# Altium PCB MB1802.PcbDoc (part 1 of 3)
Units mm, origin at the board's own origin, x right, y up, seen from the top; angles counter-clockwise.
Board outline 70 x 70 mm, 4 copper layers (Top Layer, Signal Layer 1, Signal Layer 2, Bottom Layer), stack 1.56 mm thick; 220 components, 159 nets, 974 pads, 563 vias.
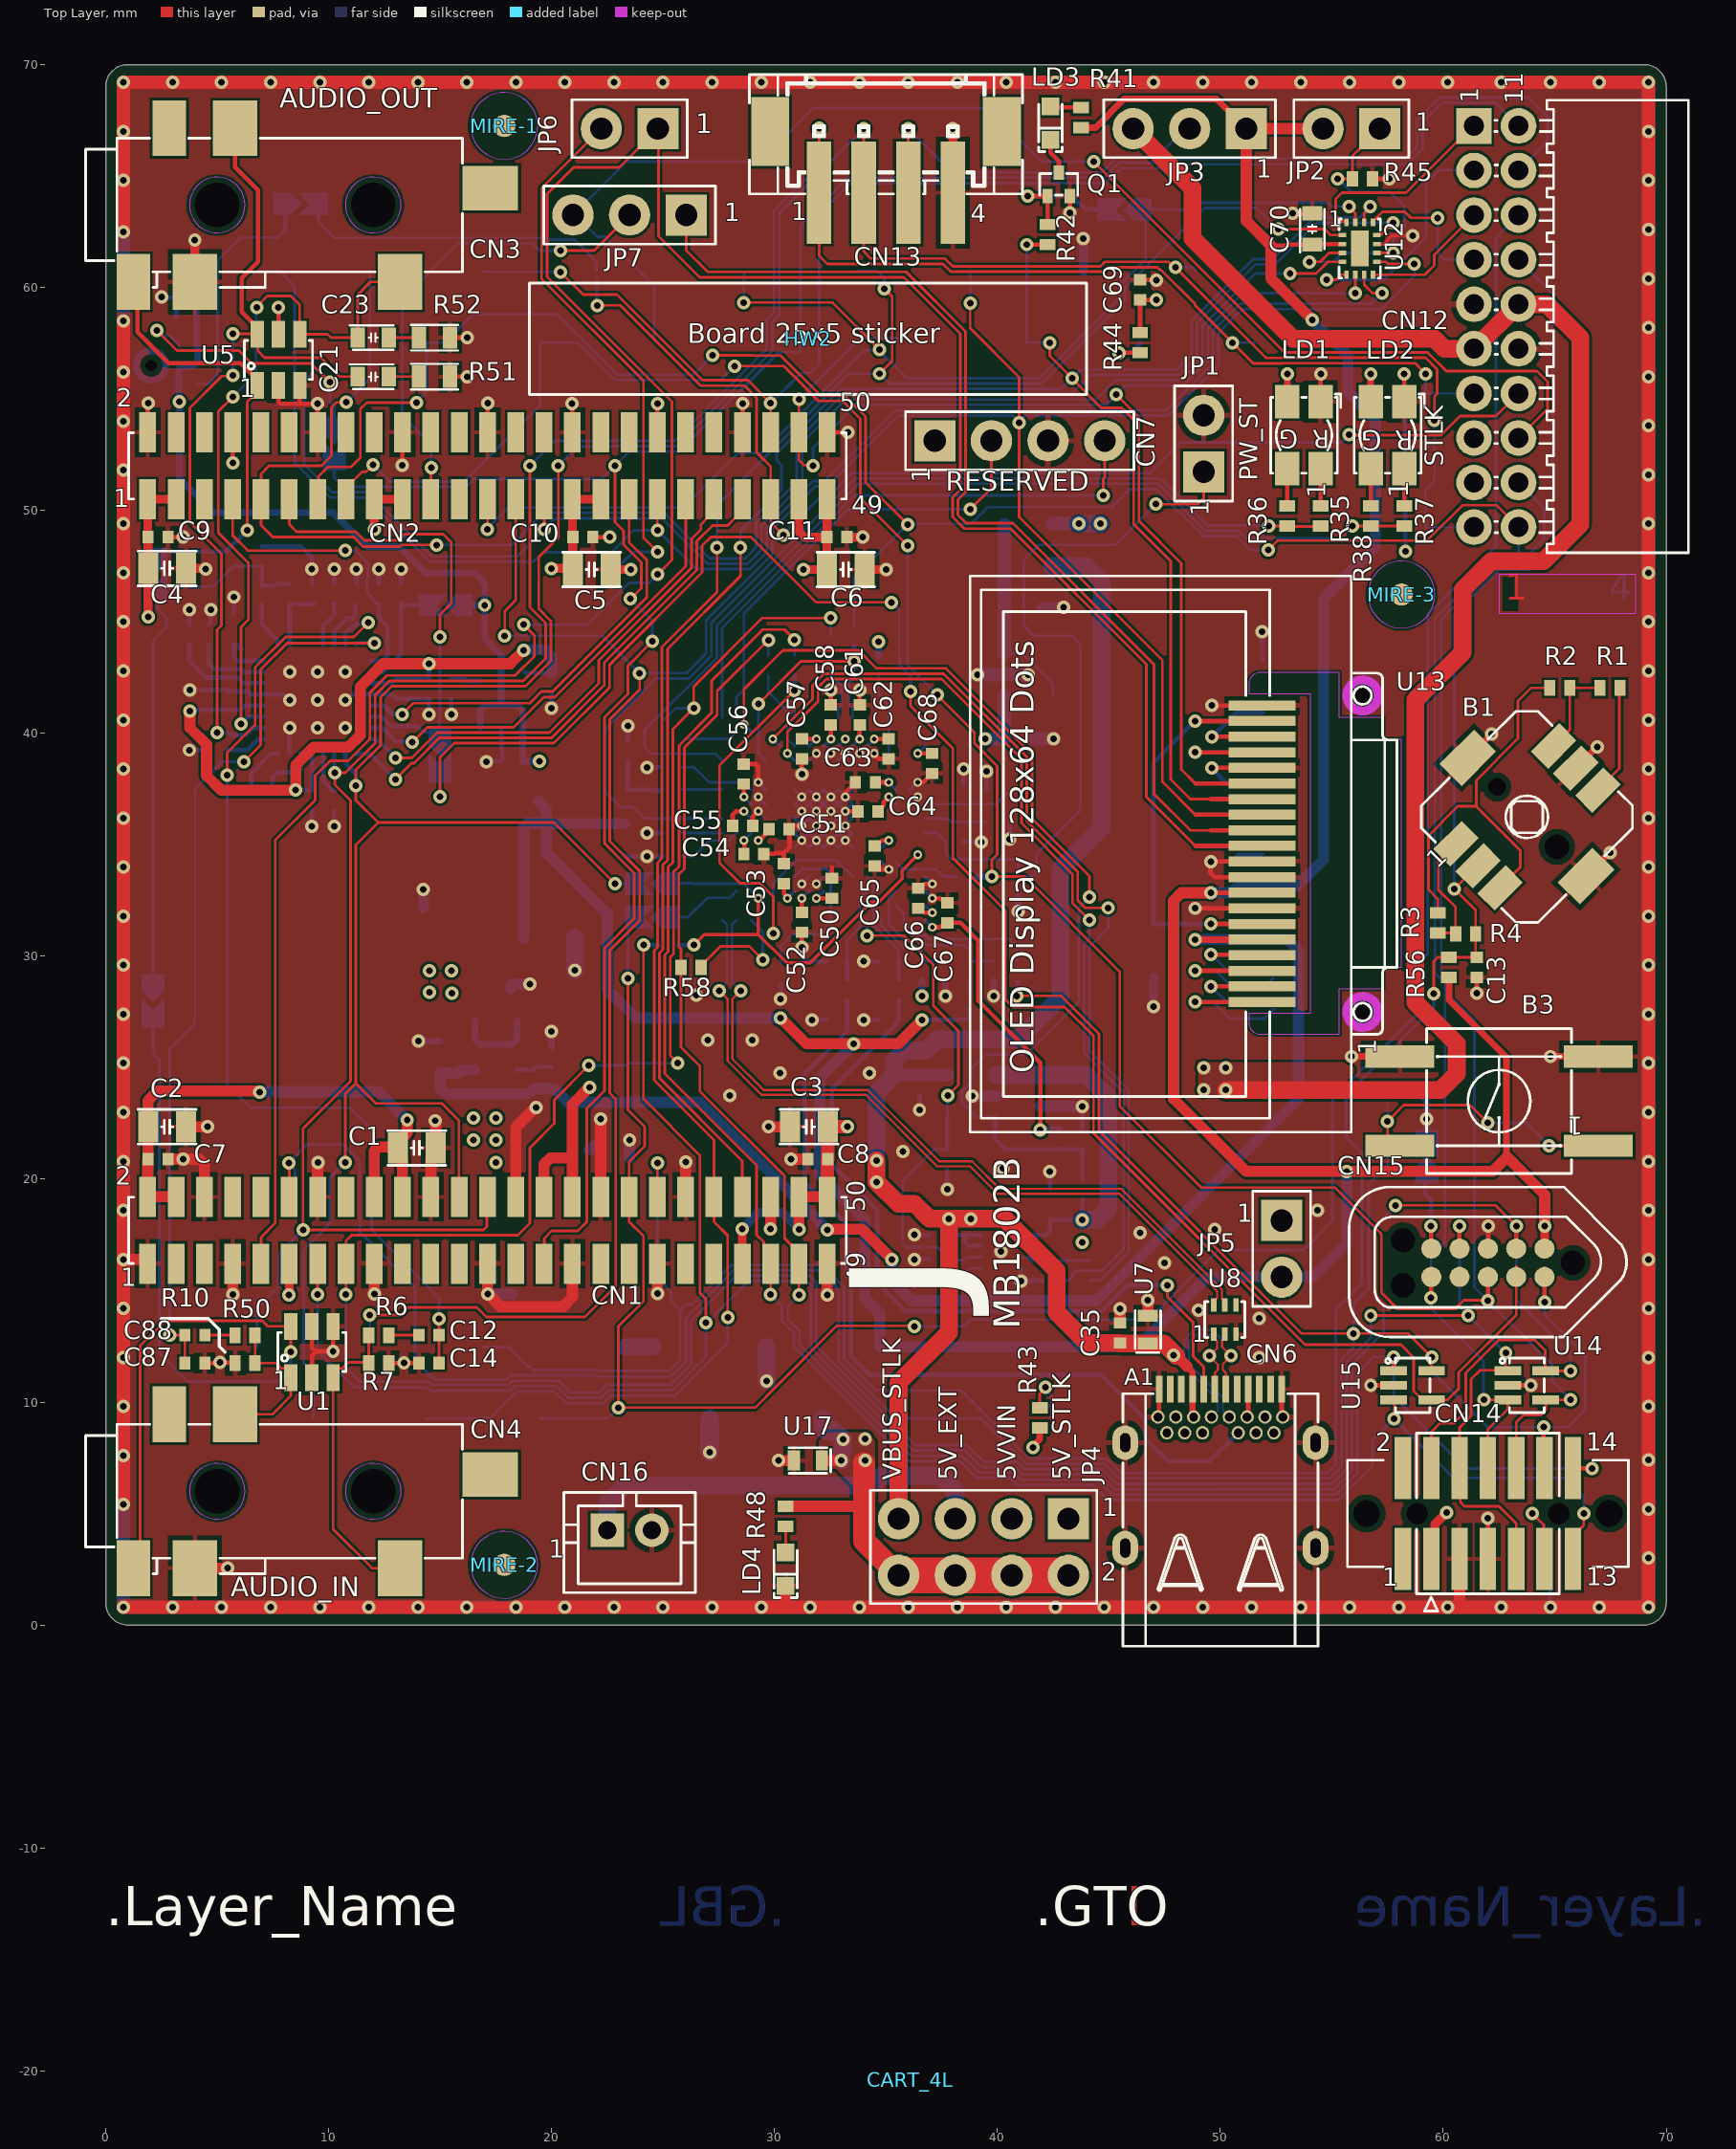
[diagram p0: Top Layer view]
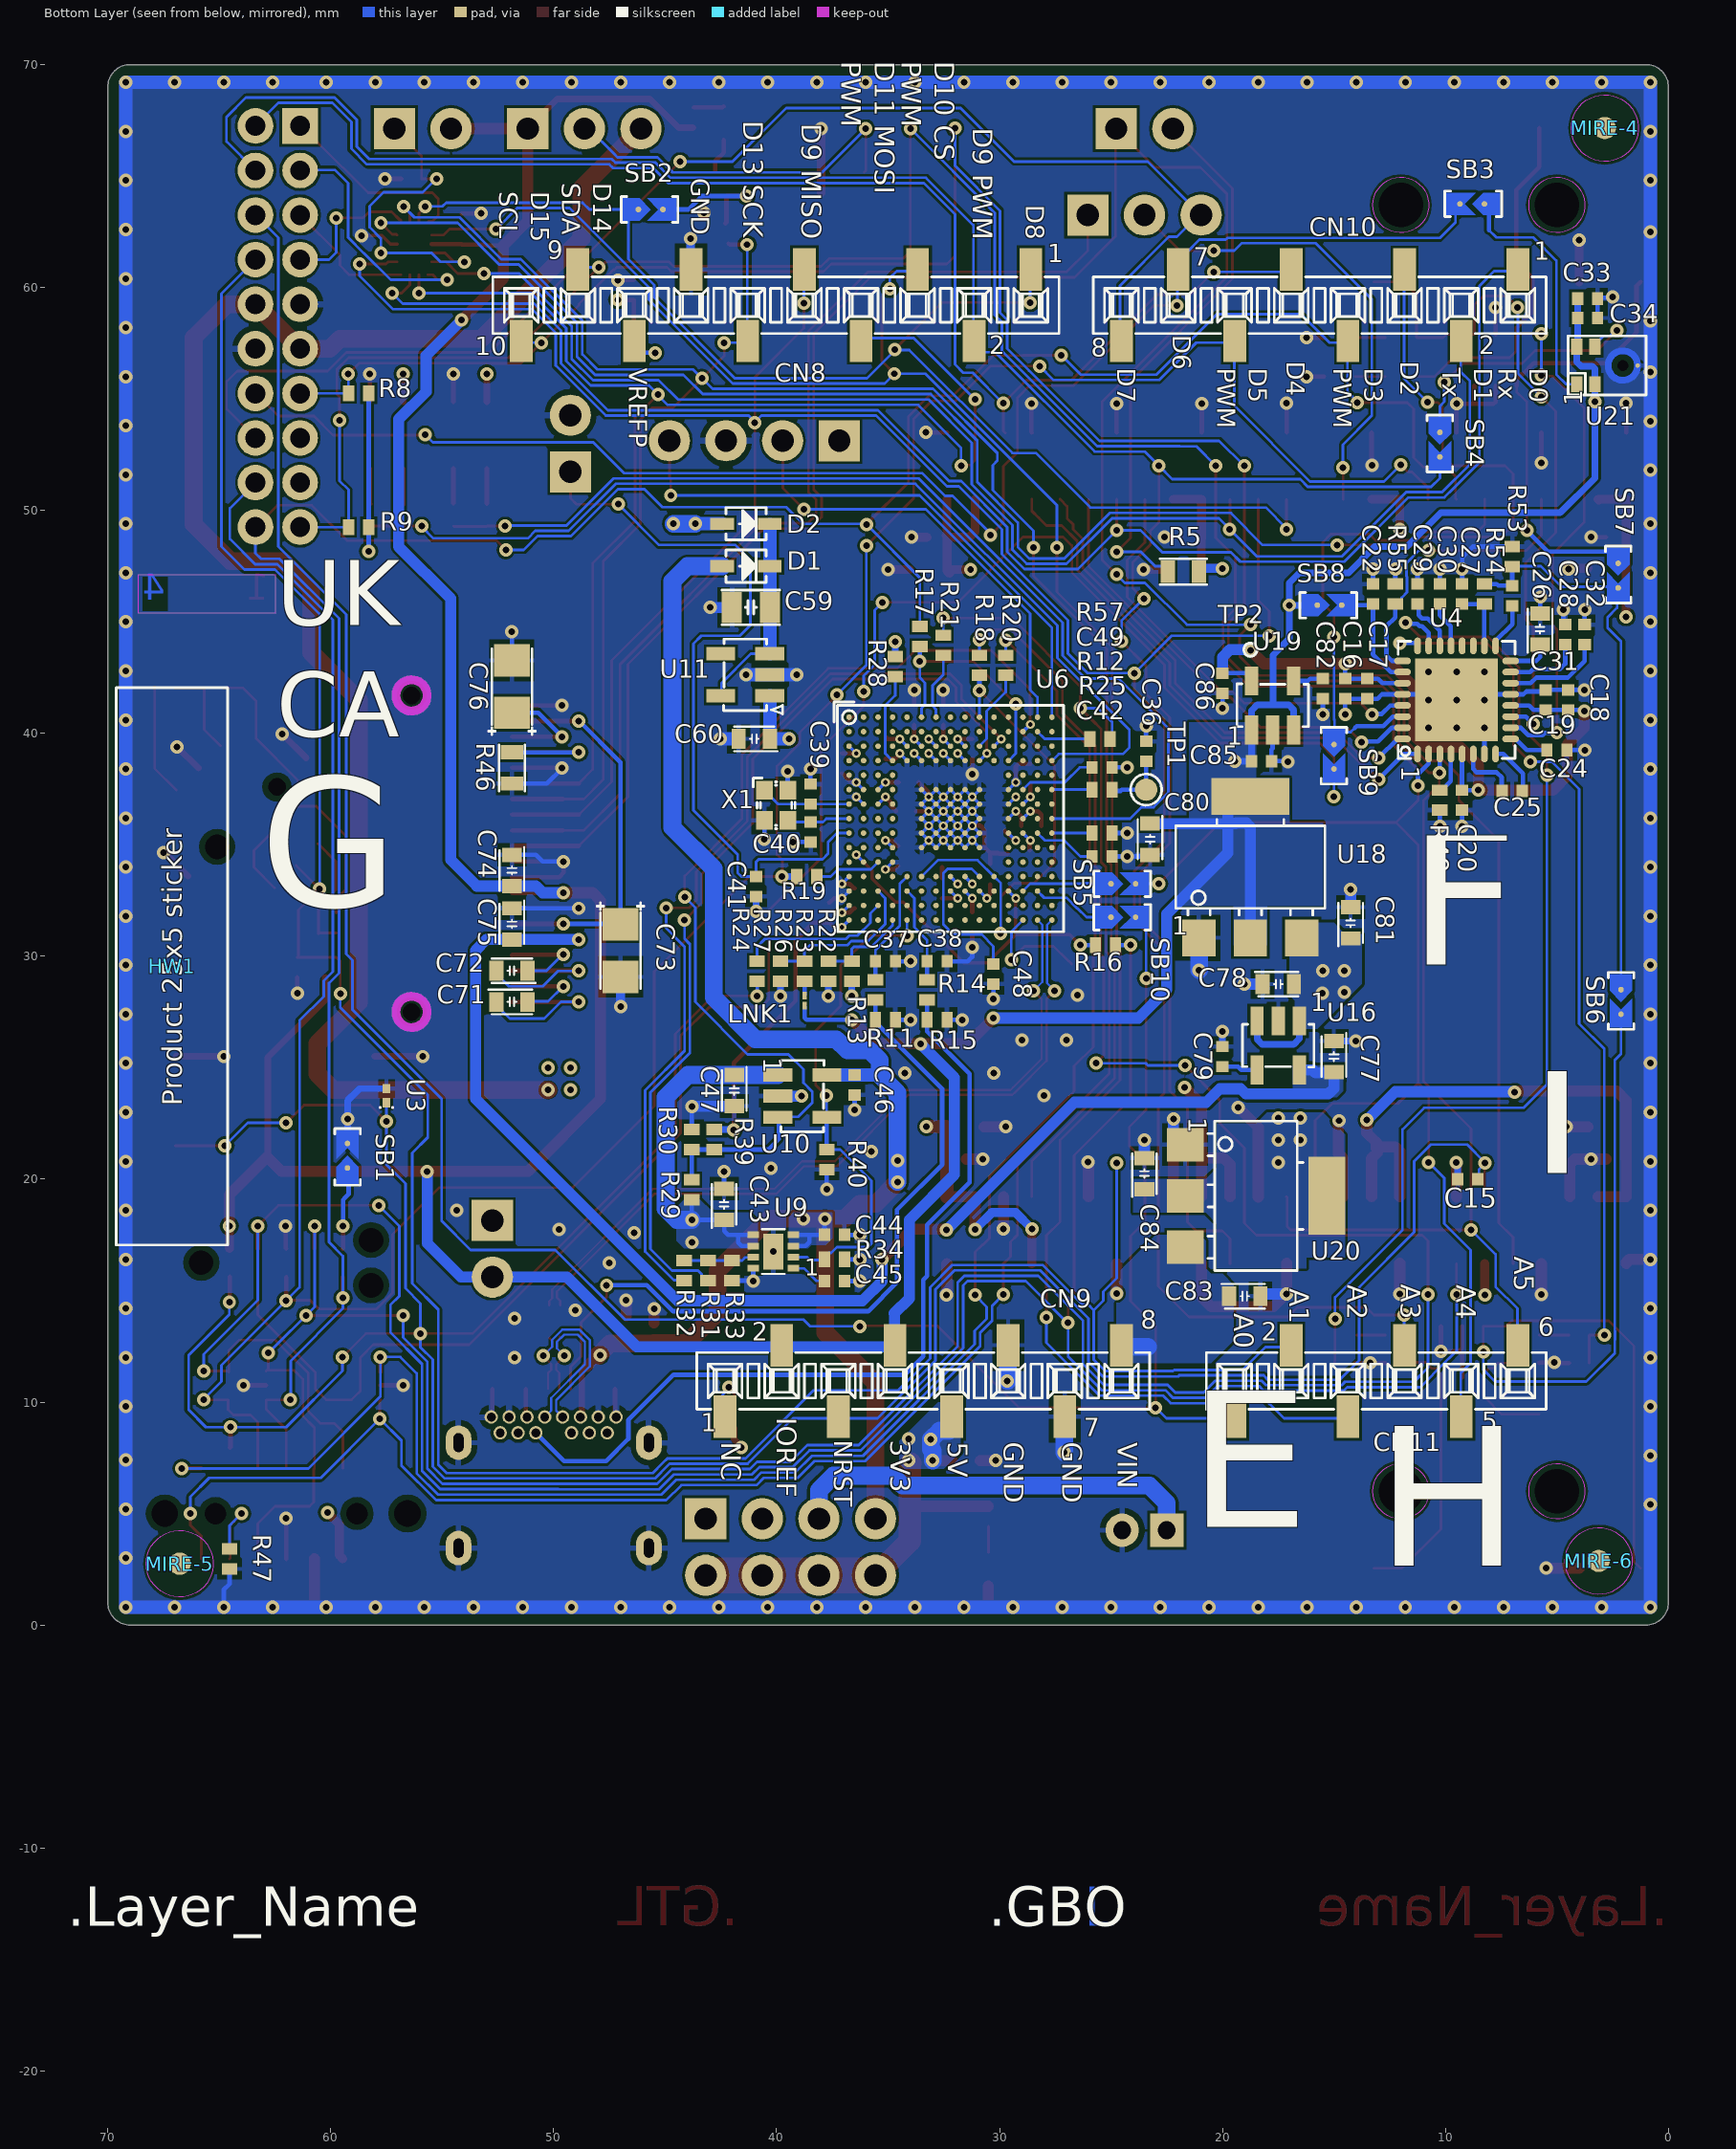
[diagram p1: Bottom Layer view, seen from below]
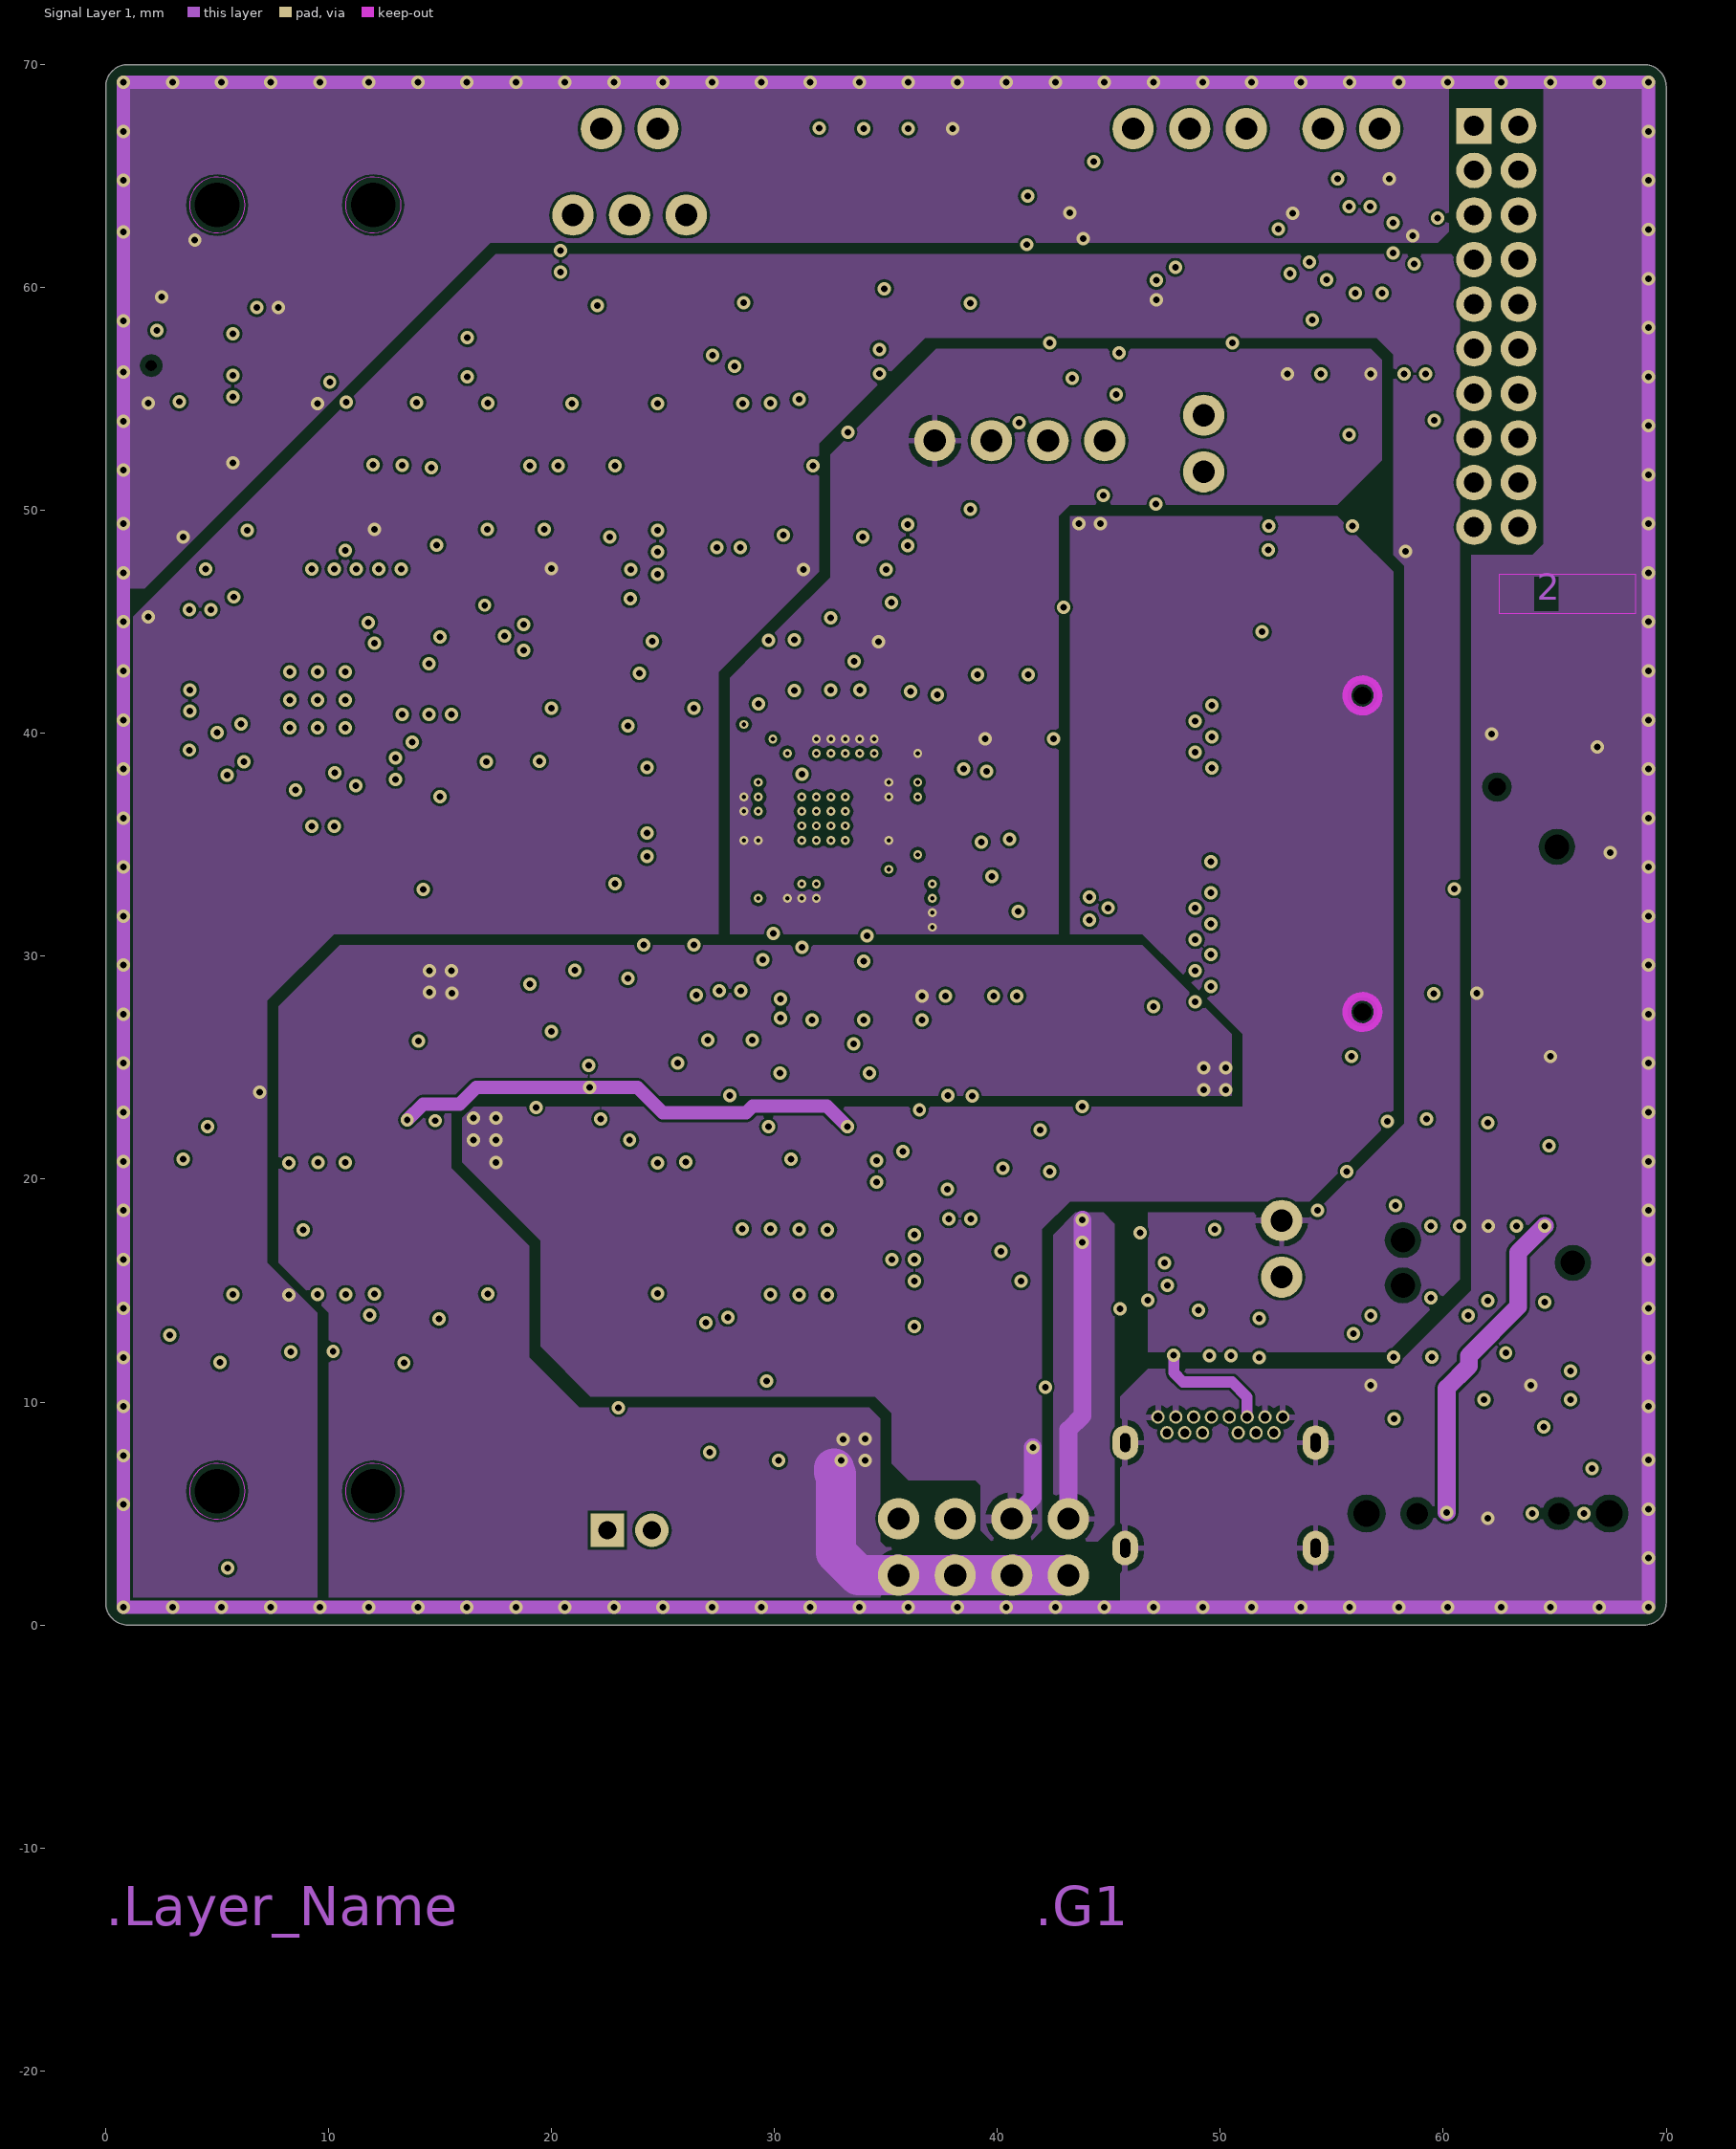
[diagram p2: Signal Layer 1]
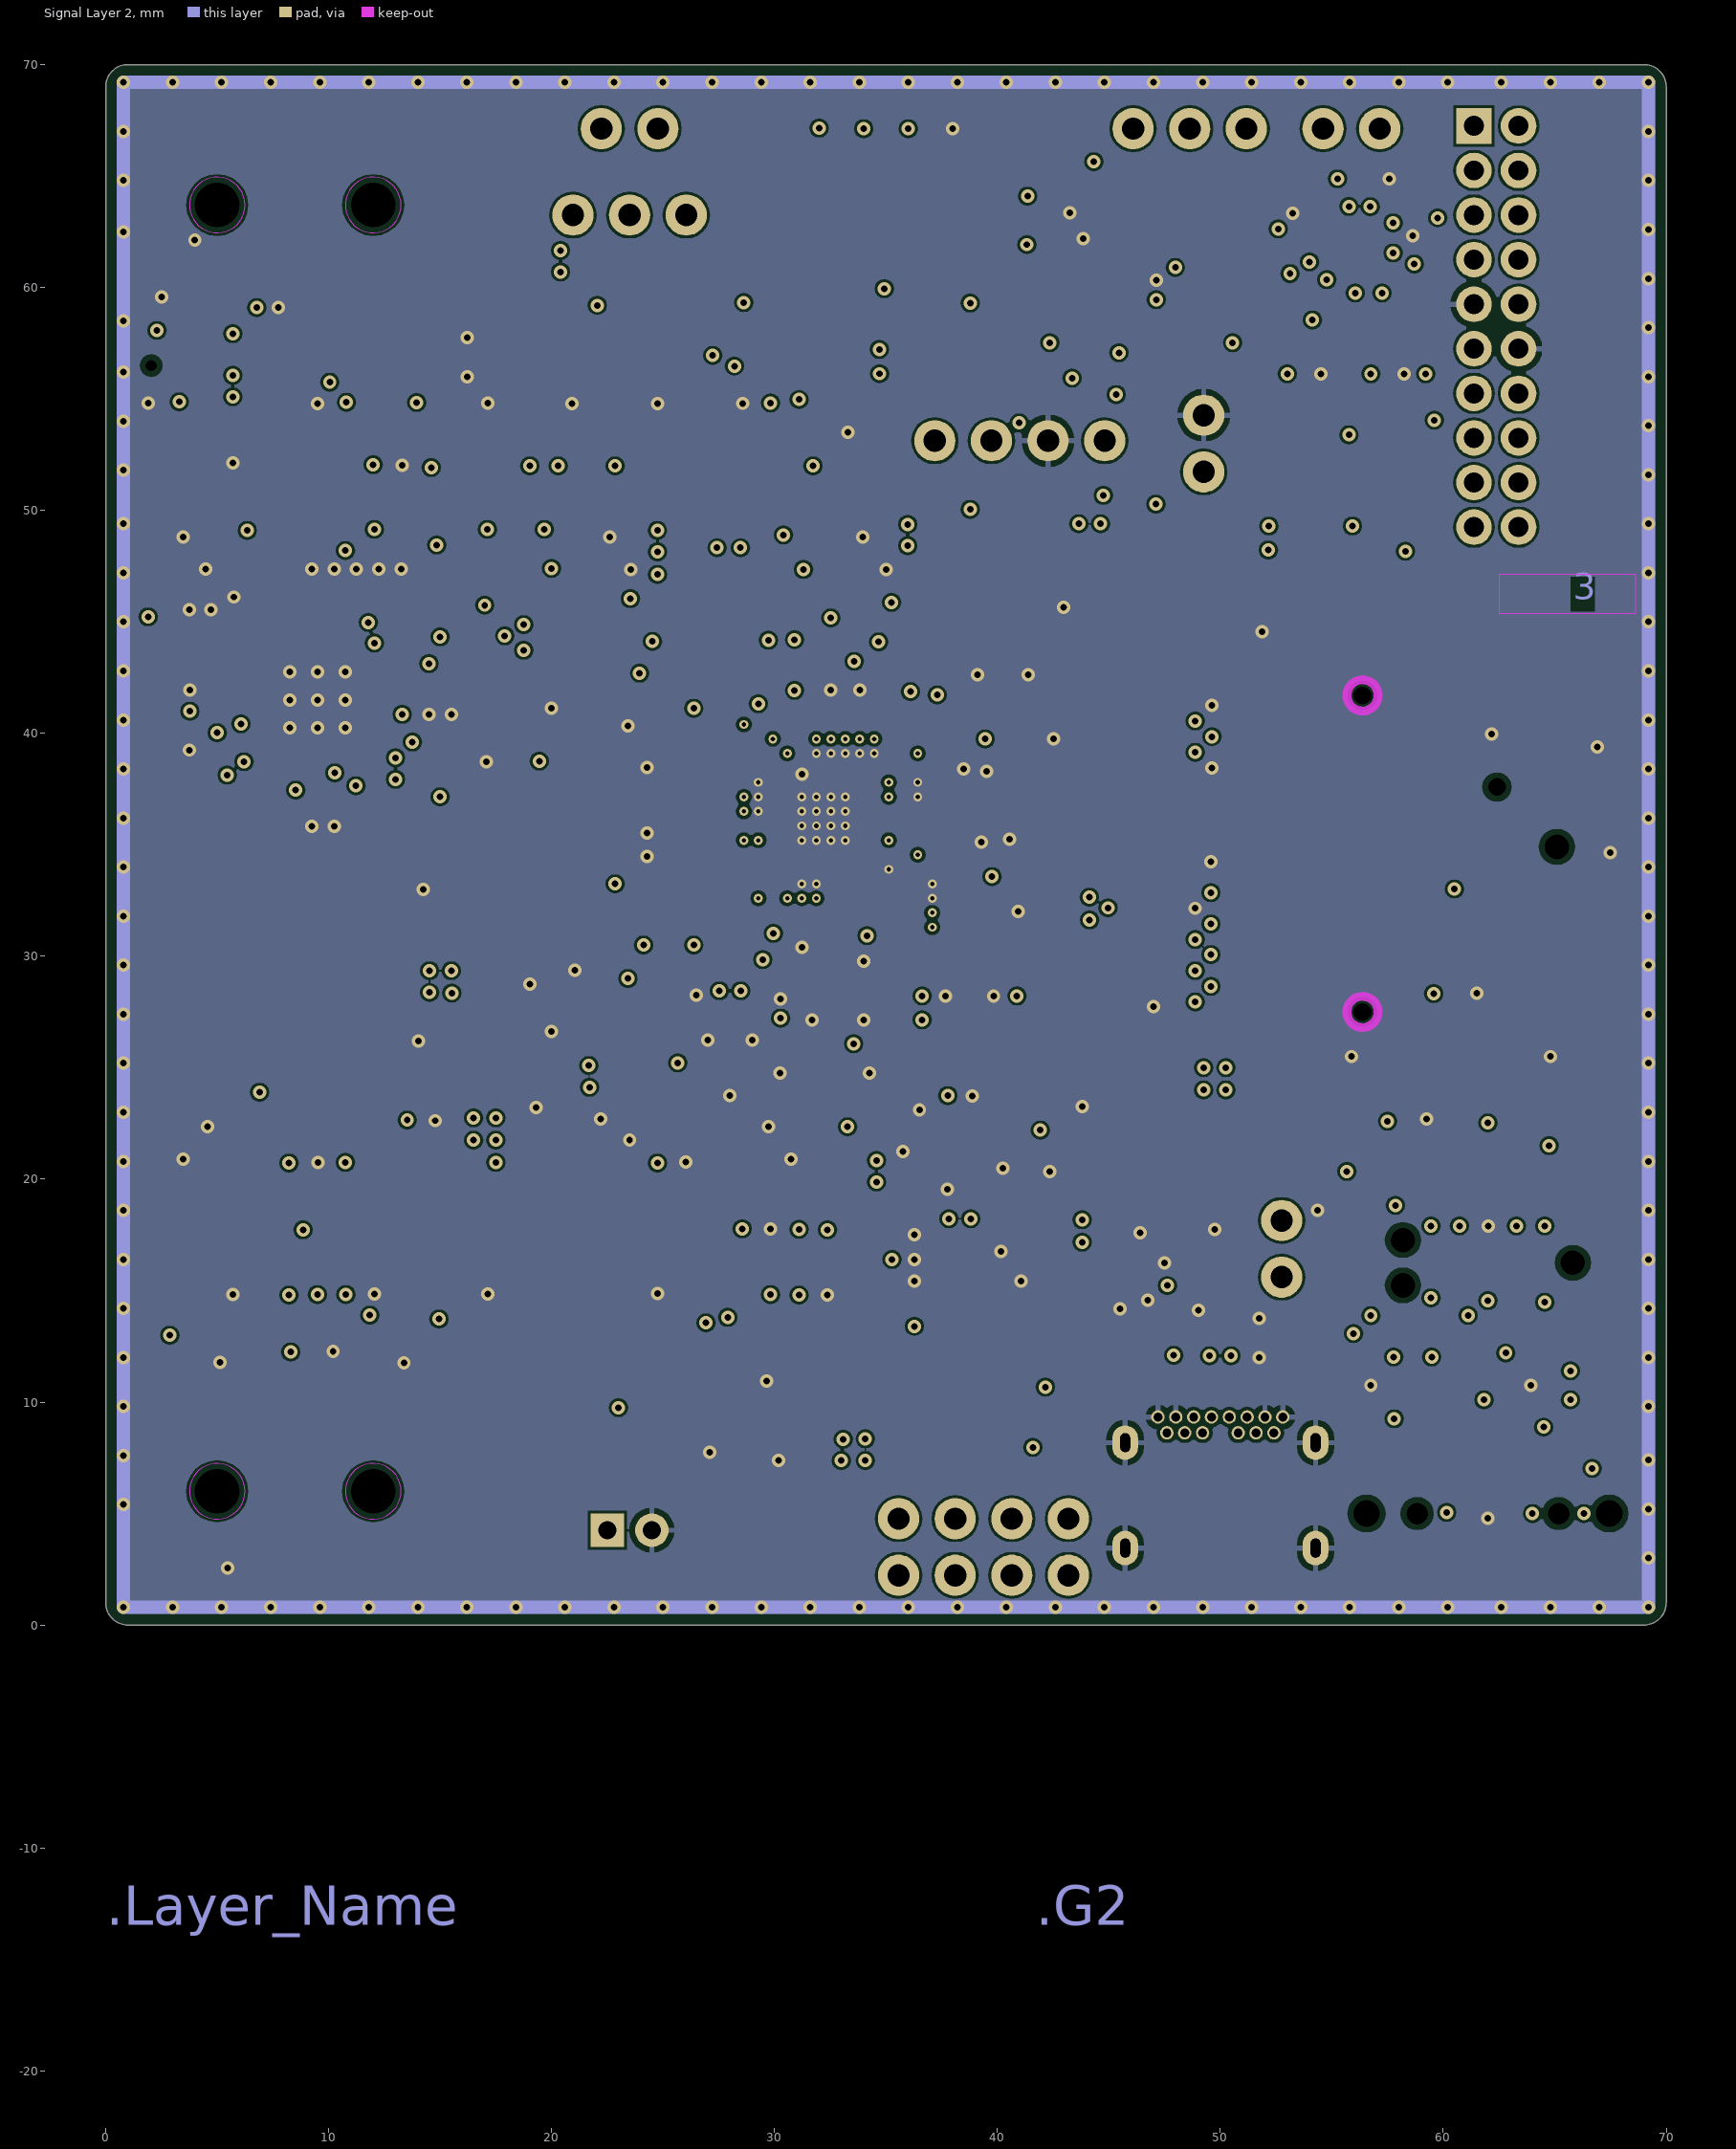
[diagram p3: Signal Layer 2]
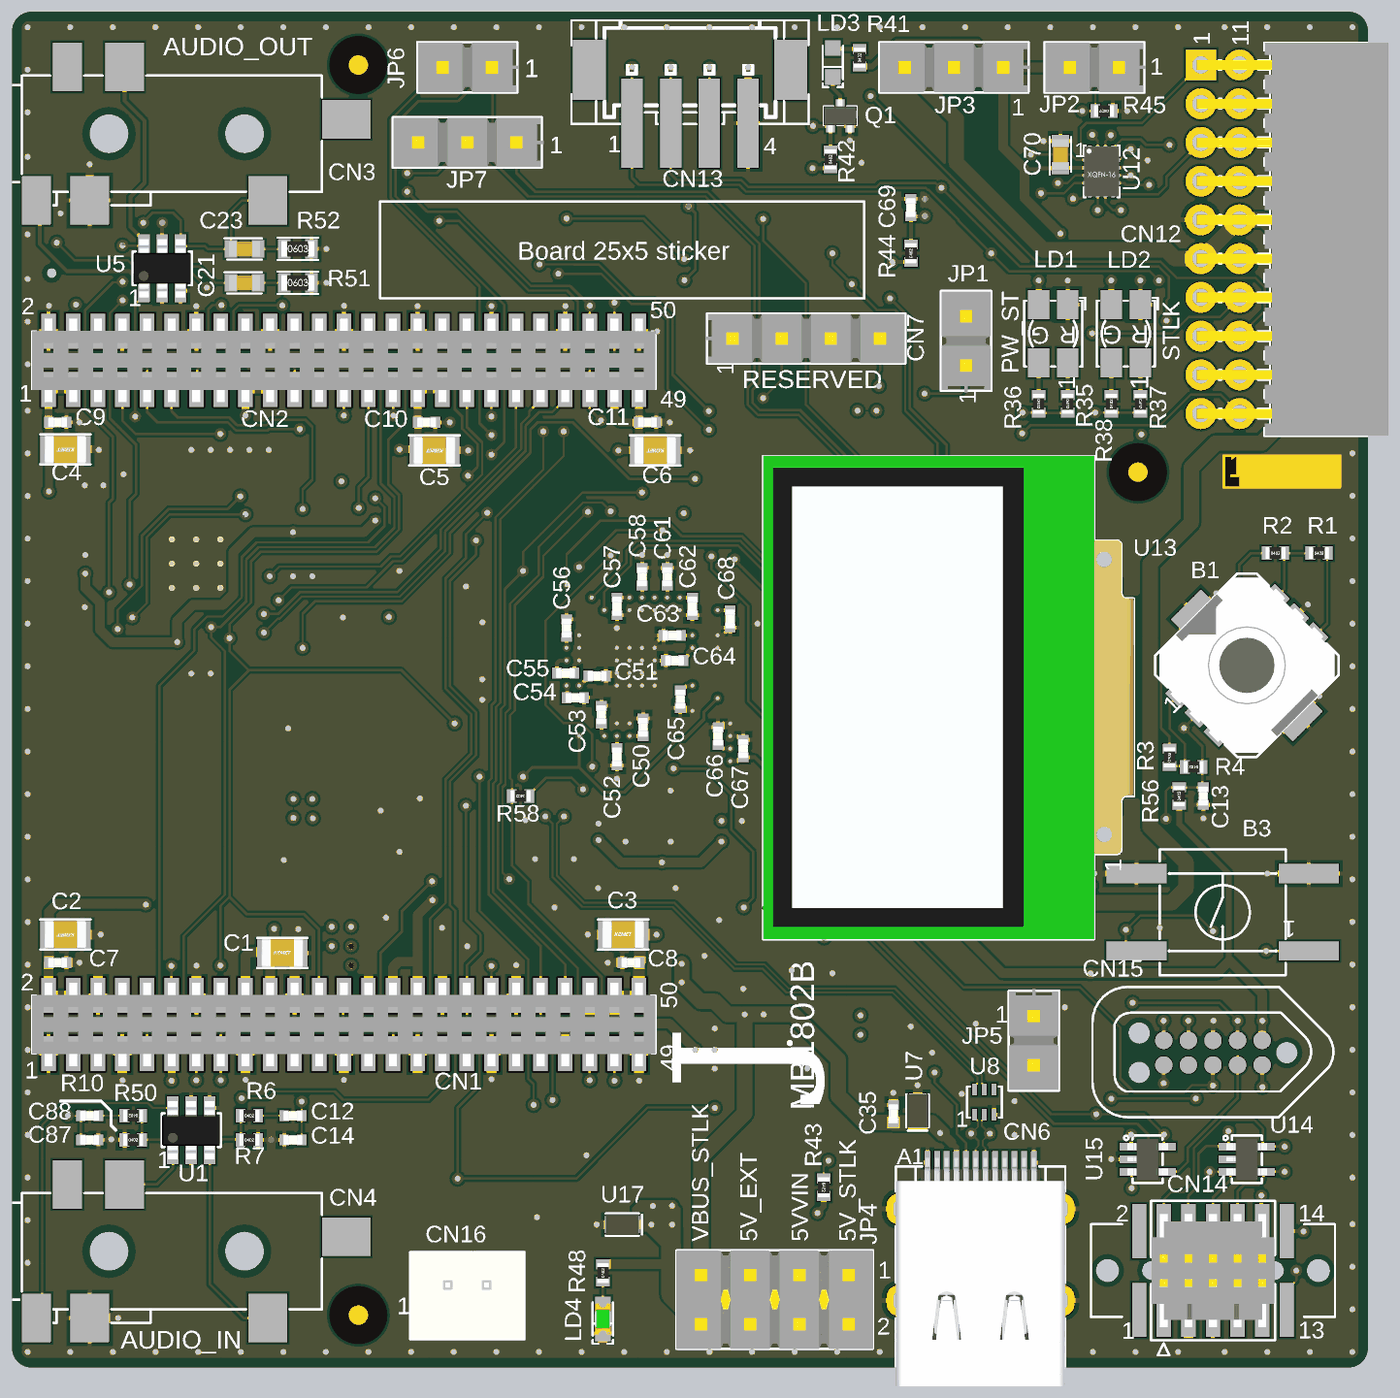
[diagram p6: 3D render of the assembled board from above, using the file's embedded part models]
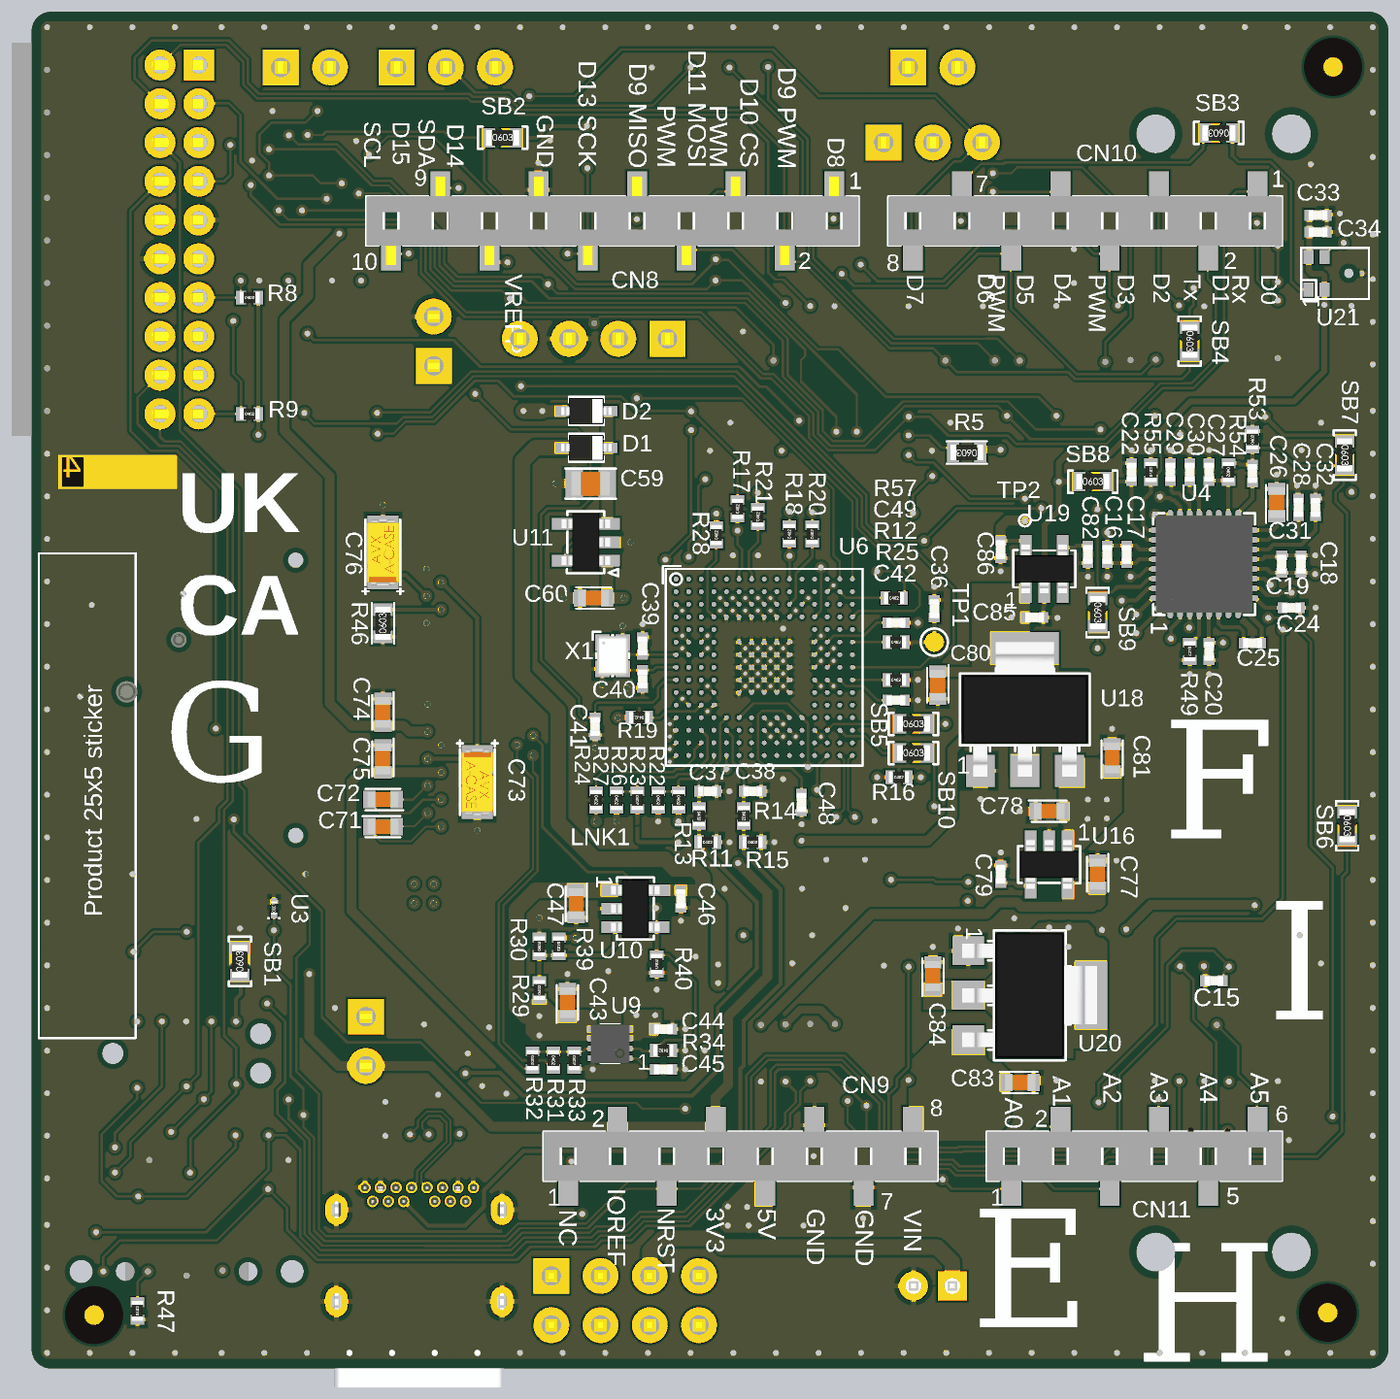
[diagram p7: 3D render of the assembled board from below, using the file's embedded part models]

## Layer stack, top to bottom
Top Solder: solder mask 0.02, Solder Resist, Dk 3.5
Top Layer: signal copper 0.054
Dielectric 1: prepreg 0.076, 1080HR RC68, Dk 4.2
Signal Layer 1: signal copper 0.035
Dielectric 2: core 1.23, FR4, Dk 4.5
Signal Layer 2: signal copper 0.035
Dielectric 3: prepreg 0.076, 1080HR RC68, Dk 4.2
Bottom Layer: signal copper 0.054
Bottom Solder: solder mask 0.02, Solder Resist, Dk 3.5

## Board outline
0,1 0,1.5 0,69 cw(c1,69) 1,70 69,70 cw(c69,69) 70,69 70,1 cw(c69,1) 69,0 1,0 cw(c1,1)

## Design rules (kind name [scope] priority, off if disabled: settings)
BoardOutlineClearance [All] p1: gap=0.5 ignorepadtopadclearanceinfootprint=FALSE
Clearance Clearance_Default_Same-net [All] p1: gap=0.12 ignorepadtopadclearanceinfootprint=TRUE except(0: SMDPad-Via SMDPad-Hole; 0.1: THPad-Via; 0.24: Arc-Hole Track-Hole; 0.25: THPad-Hole Via-Via Via-Hole Fill-Hole Poly-Hole Region-Hole Text-Hole)
Clearance Clearance_Default [All] p2: gap=0.12 ignorepadtopadclearanceinfootprint=TRUE except(0.2: Arc-Hole Track-Hole SMDPad-Hole THPad-Hole Via-Hole Fill-Hole Poly-Hole Region-Hole Text-Hole; 0.25: Via-Via)
ComponentClearance [All] p1: gap=0 collisioncheckmode=3 verticalgap=0 showdistances=FALSE
DiffPairsRouting DiffPairsRouting_STLK_USB_90R [InDifferentialPairClass('DPC__STLK_USB-90R')] p1: maxlimit=0.12 minlimit=0.12 mostfreqgap=0.12 toplayer_minwidth=0.1 toplayer_maxwidth=0.1 toplayer_prefwidth=0.1 midlayer1_minwidth=0.1 midlayer1_maxwidth=0.1 midlayer1_prefwidth=0.1 midlayer4_minwidth=0.1 midlayer4_maxwidth=0.1 midlayer4_prefwidth=0.1 bottomlayer_minwidth=0.1 bottomlayer_maxwidth=0.1 bottomlayer_prefwidth=0.1 maxuncoupledlength=12.7
Height Height_5MM_BOTTOM [OnBottomLayer and WithinRoom('HMAX 5MM')] p1: minheight=0 maxheight=5 prefheight=5
Height [All] p2: minheight=0 maxheight=40 prefheight=40
HoleSize [All] p1: absolutevalues=TRUE maxlimit=10 minlimit=0.025 maxpercent=80.000 minpercent=20.000
HoleToHoleClearance [InDrillLayerPair('Top Layer - Bottom Layer') vs InDrillLayerPair('Top Layer - Bottom Layer')] p1: gap=0.3 allowstackedmicrovias=TRUE
MaxMinImpedance "Schematic Impedance Constraint_11" [InNet('STLK_USB_CN_P')] p1: minimum=85.00 maximum=95.00
MaxMinImpedance "Schematic Impedance Constraint_10" [InNet('STLK_USB_CN_N')] p2: minimum=85.00 maximum=95.00
MaxMinImpedance "Schematic Impedance Constraint_9" [InNet('STLK_USB_P')] p3: minimum=85.00 maximum=95.00
MaxMinImpedance "Schematic Impedance Constraint_8" [InNet('STLK_USB_N')] p4: minimum=85.00 maximum=95.00
MinimumSolderMaskSliver [All] p1: minsoldermaskwidth=0.1
PolygonConnect PolygonConnect_Default [All] p1: thpad.connectstyle=Relief thpad.reliefconductorwidth=0.25 thpad.reliefentries=4 thpad.polygonreliefangle="90 Angle" thpad.airgapwidth=0.25 smdpad.connectstyle=Relief smdpad.reliefconductorwidth=0.2 smdpad.reliefentries=4 smdpad.polygonreliefangle="90 Angle" smdpad.airgapwidth=0.2 via.connectstyle=Direct via.reliefconductorwidth=0.2 via.reliefentries=4 via.polygonreliefangle="90 Angle" via.airgapwidth=0.2
RoomDefinition RoomDefinition_STLink [False vs False] p1: confinementstyle=ConfineIn formatcopy=TRUE lockcomponents=FALSE outline 26.925,40.5 37.575,40.5 37.575,31.25 26.925,31.25
RoutingLayers STLK__USB-90R [InDifferentialPairClass('DPC__STLK_USB-90R')] p1: top layer_v5=TRUE mid layer 1_v5=FALSE mid layer 4_v5=FALSE bottom layer_v5=TRUE
RoutingVias RoutingVias_PTH_L1-4_STLink [WithinRoom('RoomDefinition_STLink')and TouchesRoom('RoomDefinition_STLink')] p1: holewidth=0.2 width=0.45 viastyle="Through Hole" minholewidth=0.2 minwidth=0.45 maxholewidth=0.2 maxwidth=0.45 useviatemplates=TRUE viatemplateguid#1={76AE961C-B94A-4189-ABBD-1D46B8F7D8D9} viatemplateguid#2={A56F66F5-4D5B-4070-861C-FD4046CCDA41} viatemplatename#1=v40h20m0mx0 viatemplatename#2=v60h30m35mx35
RoutingVias RoutingVias_PTH_L1-4_Default_1 [All] p2: holewidth=0.2 width=0.45 viastyle="Through Hole" minholewidth=0.2 minwidth=0.45 maxholewidth=0.2 maxwidth=0.45 useviatemplates=TRUE viatemplateguid#1={A56F66F5-4D5B-4070-861C-FD4046CCDA41} viatemplatename#1=v60h30m35mx35
SilkToSilkClearance [All] p1: silktosilkclearance=0.2
SilkToSolderMaskClearance [IsPad] p1: minsilkscreentomaskgap=0.2 clearancetoexposedcopper=TRUE
SolderMaskExpansion [All] p1: expansion=0.102 istentingtop=FALSE
UnRoutedNet [All] p1: checkbadconnections=TRUE
ViasUnderSMD [All] p1: allowed=TRUE
Width Width_Default [All] p1: maxlimit=10 minlimit=0.12 preferedwidth=0.12
20 further rules are at their usual default settings.

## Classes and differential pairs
component class U_STMod+: C70 CN12 CN13 HW1 HW2 JP2 JP3 R45 U12
component class U_STLink_V3EC: C35 C36 C37 C38 C39 C40 C41 C42 C43 C44 C45 C46 C47 C48 C49 C50 C51 C52 C53 C54 C55 C56 C57 C58 C59 C60 C61 C62 C63 C64 C65 C66 C67 C68 CN6 CN7 D1 D2 JP1 LD1 LD2 LNK1 R11 R12 R13 R14 R15 R16 R17 R18 R19 R20 R21 R22 R23 R24 R25 R26 R27 R28 R29 R30 R31 R32 R33 R34 R35 R36 R37 R38 R39 R40 R57 R58 TP1 U6 U7 U8 U9 U10 U11 X1
component class U_OLED: C71 C72 C73 C74 C75 C76 R46 U13
component class U_MCU: C1 C2 C3 C4 C5 C6 C7 C8 C9 C10 C11 CN1 CN2 HW5 HW6 JP6 JP7 R5 R8 R9 SB5 SB9 SB10
component class U_MCU_Clock&Reset: B1 B3 C13 C15 R1 R2 R3 R4 R56 U3
component class U_External_Debug_Interface: CN14 CN15 R47 SB1 U14 U15
component class U_Board_Power: C77 C78 C79 C80 C81 C82 C83 C84 C85 C86 CN16 HW3 HW4 JP4 JP5 LD4 R48 TP2 U16 U17 U18 U19 U20
component class U_Audio_Codec: C12 C14 C16 C17 C18 C19 C20 C21 C22 C23 C24 C25 C26 C27 C28 C29 C30 C31 C32 C33 C34 C87 C88 CN3 CN4 R6 R7 R10 R49 R50 R51 R52 R53 R54 R55 SB3 SB4 SB6 SB7 SB8 U1 U4 U5 U21
component class U_Arduino: C69 CN8 CN9 CN10 CN11 LD3 Q1 R41 R42 R43 R44 SB2
differential pair STLK_USB: +STLK_USB_P -STLK_USB_N
differential pair STLK_USB_CN: +STLK_USB_CN_P -STLK_USB_CN_N

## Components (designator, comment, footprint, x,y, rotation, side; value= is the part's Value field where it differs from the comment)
B1 "Joystick MT-008A_M" SWI_XIEJIA_MT-008A_6P 63.75,36.25 r45 top value=MT-008A
B3 "SW_BLACK_KSC321GLFS" SWI_C&K_KSC321GLFS_BLACK 62.5,23.5 r180 top value=KSC321GLFS
C1 "Capacitor" C0805_H0P85 13.95,21.4 r0 top value=1uF
C2 "Capacitor" C0805_H0P85 2.75,22.35 r180 top value=1uF
C3 "Capacitor" C0805_H0P85 31.55,22.35 r0 top value=1uF
C4 "Capacitor" C0805_H0P85 2.75,47.4 r180 top value=1uF
C5 "Capacitor" C0805_H0P85 21.8,47.35 r180 top value=1uF
C6 "Capacitor" C0805_H0P85 33.2,47.35 r180 top value=1uF
C7 "Capacitor" C0402 2.35,20.9 r180 top value=100nF
C8 "Capacitor" C0402 31.95,20.9 r180 top value=100nF
C9 "Capacitor" C0402 2.35,48.8 r180 top value=100nF
C10 "Capacitor" C0402 21.4,48.8 r180 top value=100nF
C11 "Capacitor" C0402 32.8,48.8 r180 top value=100nF
C12 "Capacitor" C0402 14.5,13 r0 top value=1uF
C13 "Capacitor" C0402 61.5,29.5 r90 top value=10nF
C14 "Capacitor" C0402 14.5,11.75 r0 top value=1.8nF
C15 "Capacitor" C0402 9,20 r180 bottom value=100nF
C16 "Capacitor" C0402 14.5,42 r90 bottom value=1uF
C17 "Capacitor" C0402 13.5,42 r90 bottom value=100nF
C18 "Capacitor" C0402 4.5,41.5 r270 bottom value=1uF
C19 "Capacitor" C0402 5.5,41.5 r270 bottom value=100nF
C20 "Capacitor" C0402 9.25,37 r90 bottom value=100nF
C21 "Capacitor" C0603 12,56 r180 top value=22nF
C22 "Capacitor" C0402 13.25,46.25 r90 bottom value=100nF
C23 "Capacitor" C0603 12,57.75 r180 top value=22nF
C24 "Capacitor" C0402 5,39.25 r0 bottom value=1uF
C25 "Capacitor" C0402 7.005,37.425 r0 bottom value=1uF
C26 "Capacitor" C0402 7.005,46.175 r270 bottom value=1uF
C27 "Capacitor" C0402 9.25,46.25 r90 bottom value=100nF
C28 "Capacitor" C0402 4.63,44.425 r270 bottom value=1uF
C29 "Capacitor" C0402 11.25,46.25 r270 bottom value=150pF
C30 "Capacitor" C0402 10.25,46.25 r270 bottom value=150pF
C31 "Capacitor" C0603 5.755,44.675 r270 bottom value=10uF
C32 "Capacitor" C0402 3.755,44.425 r270 bottom value=1uF
C33 "Capacitor" C0402 3.625,59.5 r0 bottom value=100nF
C34 "Capacitor" C0402 3.625,58.625 r180 bottom value=1uF
C35 "Capacitor" C0402 45.5,13.1 r90 top value=100pF
C36 "Capacitor" C0402 23.425,39.2 r270 bottom value=20pF
C37 "Capacitor" C0402 35.12,29.775 r180 bottom value=10nF
C38 "Capacitor" C0402 32.8,29.775 r180 bottom value=10nF
C39 "Capacitor" C0402 38.48,37.275 r90 bottom value=2.7pF
C40 "Capacitor" C0402 38.48,35.575 r90 bottom value=2.7pF
C41 "Capacitor" C0402 40.925,33.125 r90 bottom value=100nF
C42 "Capacitor" C0402 25.4,34.475 r0 bottom value=2.2uF
C43 "Capacitor" C0603 42.355,18.875 r270 bottom value=10uF
C44 "Capacitor" C0402 37.4,17.5 r0 bottom value=100nF
C45 "Capacitor" C0402 37.4,15.425 r0 bottom value=10nF
C46 "Capacitor" C0402 36.5,24.225 r90 bottom value=100nF
C47 "Capacitor" C0603 41.9,23.975 r90 bottom value=10uF
C48 "Capacitor" C0402 30.275,29.2 r90 bottom value=2.2uF
C49 "Capacitor" C0402 25.4,38.475 r0 bottom value=2.2uF
C50 "Capacitor" C0402 32.575,33.05 r90 top value=100nF
C51 "Capacitor" C0402 30.2,35.7 r0 top value=100nF
C52 "Capacitor" C0402 31.225,31.525 r270 top value=100nF
C53 "Capacitor" C0402 30.42,33.7 r90 top value=100nF
C54 "Capacitor" C0402 29.075,34.575 r0 top value=100nF
C55 "Capacitor" C0402 28.575,35.85 r0 top value=100nF
C56 "Capacitor" C0402 28.625,38.175 r90 top value=100nF
C57 "Capacitor" C0402 31.225,39.3 r270 top value=100nF
C58 "Capacitor" C0402 32.525,40.825 r90 top value=100nF
C59 "Capacitor" C0805 41.155,45.65 r180 bottom value=2.2uF
C60 "Capacitor" C0603 41.005,39.75 r180 bottom value=10uF
C61 "Capacitor" C0402 33.825,40.825 r90 top value=100nF
C62 "Capacitor" C0402 35.125,39.3 r270 top value=100nF
C63 "Capacitor" C0402 34.075,37.8 r180 top value=100nF
C64 "Capacitor" C0402 34.2,36.5 r180 top value=100nF
C65 "Capacitor" C0402 34.5,34.5 r270 top value=100nF
C66 "Capacitor" C0402 36.45,32.6 r90 top value=100nF
C67 "Capacitor" C0402 37.75,31.95 r90 top value=100nF
C68 "Capacitor" C0402 37.075,38.65 r270 top value=100nF
C69 "" C0402 46.398,59.89 r90 top value=100nF
C70 "Capacitor" C0603 54.125,62.625 r270 top value=1uF
C71 "" C0603 51.875,27.95 r0 bottom value=1uF
C72 "" C0603 51.875,29.35 r180 bottom value=1uF
C73 "​Footprint CPOL_TAJ-A_1206_H180" CPOL_TAJ-A_1206_H180 47,30.25 r270 bottom value=4.7uF
C74 "" C0603 51.875,33.85 r90 bottom value=1uF
C75 "" C0603 51.875,31.45 r90 bottom value=1uF
C76 "​Footprint CPOL_TAJ-A_1206_H180" CPOL_TAJ-A_1206_H180 51.875,42.1 r90 bottom value=4.7uF
C77 "Capacitor" C0603 15,25.5 r90 bottom value=2.2uF
C78 "Capacitor" C0603 17.5,28.75 r0 bottom value=1uF
C79 "Capacitor" C0402 20,25.5 r90 bottom value=10nF
C80 "Capacitor" C0603 23.25,35.25 r90 bottom value=10uF
C81 "Capacitor" C0603 14.25,31.5 r270 bottom value=10uF
C82 "Capacitor" C0402 15.5,42 r90 bottom value=10nF
C83 "Capacitor" C0603 19,14.75 r0 bottom value=10uF
C84 "Capacitor" C0603 23.5,20.25 r270 bottom value=10uF
C85 "Capacitor" C0402 18.25,38.75 r0 bottom value=1uF
C86 "Capacitor" C0402 20,42.25 r90 bottom value=1uF
C87 "Capacitor" C0402 4,11.75 r0 top value=1.8nF
C88 "Capacitor" C0402 4,13 r180 top value=1uF
CART_4L "Comment" Sheetbox_4L2S -9,-25.75 r0 top
CN1 "CLP-125-02-F-D" CON_SAMTEC_CLP-125-02-F-D 17.125,17.71 r90 top locked value="Socket 25x2"
CN2 "CLP-125-02-F-D" CON_SAMTEC_CLP-125-02-F-D 17.125,52 r90 top locked value="Socket 25x2"
CN3 "Jack_PJ3028B-3_4P" CON_PHONE-JACK-3P5_HY_PJ3028B 0,63.7 r0 top value=PJ3028B-3_4P
CN4 "Jack_PJ3028B-3_4P" CON_PHONE-JACK-3P5_HY_PJ3028B 0,6 r0 top value=PJ3028B-3_4P
CN6 "USB_TYPE_C_Receptacle" CON_USB-TYPEC_WE_632723300011 50,0 r0 top value=USB_C_632723300011
CN7 "Header 4x1" CON_SAMTEC_TSW-104-07-G-S 41,53.125 r0 top
CN8 "Socket 10x1" CON_SAMTEC_SSM-110-L-SV 40.027,59.206 r0 bottom locked value=SSM-110-L-SV
CN9 "Socket 8x1" CON_SAMTEC_SSM-108-L-SV 33.423,10.947 r180 bottom locked value=SSM-108-L-SV
CN10 "Socket 8x1" CON_SAMTEC_SSM-108-L-SV 15.643,59.206 r0 bottom value=SSM-108-L-SV
CN11 "Socket 6x1" CON_SAMTEC_SSM-106-L-SV 13.103,10.947 r180 bottom locked value=SSM-106-L-SV
CN12 "Socket 10X2 STMod+" CON_SAMTEC_SQT-110-01-F-D-RA__STMOD+ 62.375,58.25 r90 top locked
CN13 "Header 4x1" CON_988-JIUBABA_A2006LF-04A 35,67 r180 top locked
CN14 "Header 7x2" CON_STDC14_Receiver_MEDIUM_WITH_MIPI10_3D 62,5 r0 top locked value="MIPI10 on STDC14 footprint"
CN15 "Tag-10-C" CON_TAG-C_TC2050-IDC-NL 62,16.25 r180 top value="Header 5x2"
CN16 "Header 2x1" CON_JST_B2B-PH-K-S 23.5,4.25 r0 top value=B2B-PH-K-S
D1 "SCHOTTKY_1A_2K" DIO_SOD323_1A_2K 41.375,47.5 r180 bottom value=BAT20JFILM
D2 "SCHOTTKY_1A_2K" DIO_SOD323_1A_2K 41.375,49.4 r180 bottom value=BAT20JFILM
HW1 "Comment" STICKER_PRODUCT_25X5 67.125,29.55 r270 bottom value=MB1801
HW2 "STICKER_BOARD" STICKER_BOARD_25X5 31.5,57.7 r0 top value="Sticker board"
JP1 "Jumper_Header 2x1" CON_SAMTEC_TSW-102-07-G-S 49.25,53 r90 top value="Header 2x1"
JP2 "Jumper_Header 2x1" CON_SAMTEC_TSW-102-07-G-S 55.875,67.125 r180 top value="Shunt not fitted"
JP3 "Shunt Fitted 1-2" CON_SAMTEC_TSW-103-07-F-S 48.625,67.125 r180 top
JP4 "Jumper_Header 4x2 Fitted 1-2" CON_SAMTEC_TSW-104-07-X-D 39.375,3.5 r180 top value="Header 4x2"
JP5 "Jumper_Header 2x1" CON_SAMTEC_TSW-102-07-G-S 52.75,16.875 r270 top value="Shunt for curent measurement."
JP6 "Jumper_Header 2x1" CON_SAMTEC_TSW-102-07-G-S 23.5,67.125 r180 top value="Header 2x1"
JP7 "Shunt Fitted 1-2" CON_SAMTEC_TSW-103-07-F-S 23.5,63.25 r180 top
LD1 "LED_BICOLOR" LED_BI-GR_WE-150141SV73110 53.75,53.375 r180 top value="Green / Red"
LD2 "LED_BICOLOR" LED_BI-GR_WE-150141SV73110 57.5,53.375 r180 top value="Green / Red"
LD3 "LED_blue" LED_0603_VISHAY_VLMB1300-GS08_BLUE_1A2K_H0P8 42.375,67.375 r270 top value=BLUE
LD4 "" LED_0603_OSRAM_LG-Q396-PS-35_GREEN_1A2K_H0P4 30.5,2.5 r270 top value=GREEN
LNK1 "link_200" LINK200 38.75,28.005 r180 bottom
MIRE-1 "Comment" MIRE_PLACE_SMD_1MM 17.875,67.25 r0 top
MIRE-2 "Comment" MIRE_PLACE_SMD_1MM 17.875,2.7 r0 top
MIRE-3 "Comment" MIRE_PLACE_SMD_1MM 58.125,46.225 r0 top
MIRE-4 "Comment" MIRE_PLACE_SMD_1MM 2.85,67.15 r180 bottom
MIRE-5 "Comment" MIRE_PLACE_SMD_1MM 66.775,2.75 r180 bottom
MIRE-6 "Comment" MIRE_PLACE_SMD_1MM 3.125,2.875 r180 bottom
Q1 "DTC043ZEBTL" NPN_SOT416-FL_EMT3F_1616_SC89 42.75,64.625 r0 top
R1 "Resistor" R0402 67.475,42.043 r0 top value=5K1
R2 "Resistor" R0402 65.225,42.043 r0 top value=1K8
R3 "Resistor" R0402 59.75,31.5 r90 top value=820R
R4 "Resistor" R0402 61,31 r180 top value=510R
R5 "" R0603 21.75,47.25 r0 bottom value=10K
R6 "Resistor" R0402 12.25,13 r0 top value=100R
R7 "Resistor" R0402 12.25,11.75 r0 top value=100K
R8 "Resistor" R0402 58.75,55.25 r180 bottom value=4K7
R9 "Resistor" R0402 58.75,49.25 r180 bottom value=4K7
R10 "Resistor" R0402 6.25,11.75 r0 top value=100K
R11 "Resistor" R0402 35.12,27.15 r180 bottom value=5K1
R12 "Resistor" R0402 25.4,37.475 r180 bottom value=100R
R13 "Resistor" R0402 35.57,28.5 r270 bottom value=100K
R14 "Resistor" R0402 33.25,28.5 r270 bottom value=100K
R15 "Resistor" R0402 32.8,27.15 r180 bottom value=5K1
R16 "Resistor" R0402 25.25,30.5 r180 bottom value=33R
R17 "Resistor" R0402 33.575,44.35 r90 bottom value=0R
R18 "Resistor" R0402 30.9,43.05 r90 bottom value=33R
R19 "Resistor" R0402 38.65,33.575 r0 bottom value=33R
R20 "Resistor" R0402 29.725,43.05 r90 bottom value=0R
R21 "Resistor" R0402 32.525,43.95 r90 bottom value=33R
R22 "Resistor" R0402 36.625,29.325 r270 bottom value=5K1
R23 "Resistor" R0402 37.675,29.325 r270 bottom value=10K
R24 "Resistor" R0402 40.875,29.325 r270 bottom value=0R
R25 "Resistor" R0402 25.4,35.525 r180 bottom value=3K
R26 "Resistor" R0402 38.75,29.325 r270 bottom value=10K
R27 "Resistor" R0402 39.825,29.325 r270 bottom value=10K
R28 "Resistor" R0402 34.675,43 r90 bottom value=10K
R29 "Resistor" R0402 43.805,19.525 r90 bottom value=3K
R30 "Resistor" R0402 43.805,21.775 r90 bottom value=5K1
R31 "Resistor" R0402 43.08,15.9 r270 bottom value=1K8
R32 "Resistor" R0402 44.155,15.9 r270 bottom value=1K3
R33 "Resistor" R0402 42.005,15.9 r270 bottom value=3K9
R34 "Resistor" R0402 37.4,16.4 r0 bottom value=100K
R35 "Resistor" R0402 54.5,49.75 r270 top value=1K
R36 "Resistor" R0402 53,49.75 r270 top value=330R
R37 "Resistor" R0402 58.25,49.75 r270 top value=1K
R38 "Resistor" R0402 56.75,49.75 r90 top value=330R
R39 "Resistor" R0402 42.8,21.775 r270 bottom value=100K
R40 "Resistor" R0402 37.75,20.87 r90 bottom value=100K
R41 "Resistor" R0402 43.75,67.625 r90 top value=510R
R42 "" R0402 42.25,62.375 r90 top value=0R
R43 "Resistor" R0402 41.9,9.3 r270 top value=1K
R44 "" R0402 46.398,57.525 r90 top value=0R
R45 "" R0402 56.375,64.875 r180 top value=10K
R46 "" R0603 51.875,38.45 r90 bottom value=620K
R47 "Resistor" R0402 64.54,2.968 r90 bottom value=100R
R48 "" R0402 30.5,4.875 r90 top value=620R
R49 "Resistor" R0402 10.25,37 r270 bottom value=10K
R50 "Resistor" R0402 6.25,13 r180 top value=100R
R51 "Resistor" R0603 14.75,56 r0 top value=49.9R
R52 "Resistor" R0603 14.75,57.75 r0 top value=49.9R
R53 "Resistor" R0402 7.005,47.925 r90 bottom value=100K
R54 "Resistor" R0402 8.25,46.25 r270 bottom value=2K2
R55 "Resistor" R0402 12.25,46.25 r90 bottom value=10K
R56 "Resistor" R0402 60.25,29.5 r90 top value=2K
R57 "Resistor" R0402 25.5,39.75 r180 bottom value=33R
R58 "Resistor" R0402 26.25,29.5 r180 top value=0R
SB1 "" SOLDER-BRIDGE_R0603-0R 59.25,21 r90 bottom
SB2 "" SOLDER-BRIDGE_R0603-0R 45.7,63.5 r180 bottom
SB3 "" SOLDER-BRIDGE_R0603-0R 8.75,63.75 r0 bottom
SB4 "" SOLDER-BRIDGE_R0603-0R 10.25,53 r270 bottom
SB5 "" SOLDER-BRIDGE_R0603-0R 24.5,33.25 r180 bottom
SB6 "" SOLDER-BRIDGE_R0603-0R 2.125,28 r270 bottom
SB7 "" SOLDER-BRIDGE_R0603-0R 2.25,47.125 r270 bottom
SB8 "SB_ON" SOLDER-BRIDGE_R0603-0R 15.25,45.75 r180 bottom
SB9 "" SOLDER-BRIDGE_R0603-0R 15,39 r270 bottom
SB10 "" SOLDER-BRIDGE_R0603-0R 24.5,31.75 r180 bottom
TP1 "Test Point" TP_SMD_1MM 23.425,37.475 r180 bottom
TP2 "Test Point" TP_SMD_0-3MM 18.75,43.75 r180 bottom
U1 "ESDA6V1BC6" ESD_SOT23-6L 9.25,12.25 r0 top
U3 "" ESD_ST0201 57.5,23.75 r90 bottom value=ESDALC6V1-1U2
U4 "CS42L51-CNZ" ICC_QFN32-EPAD_5X5_P050 9.5,41.5 r180 bottom
U5 "ESDA6V1BC6" ESD_SOT23-6L 7.75,56.75 r0 top
U6 "STLINK-V3EC" ICC_UFBGA201_176+25_10X10_P065 32.2,36.175 r180 bottom value=STM32F723IEK6
U7 "ESD-TRANSIL" ESD_QFN1610_2N_1K_2A 46.75,13.25 r90 top value=ESDA25P35-1U1M
U8 "​" ESD_QFN-6L_1P7X1P5_P050 50.2,13.7 r0 top value=ECMF02-2AMX6
U9 "TPS259535DSG" ICC_WSON8-EPAD_2X2_P050 40.15,16.75 r0 bottom
U10 "STMPS2151STR" MOS_SOT23-5L 38.85,23.725 r270 bottom
U11 "ST730M33R" ICC_SOT23-5L_H1P45 41.405,42.625 r90 bottom
U12 "STG3692QTR" ICC_UFQFN16-EPAD_2P6X1P8_P040 56.25,61.75 r270 top
U13 "OLED_RITDISPLAY_9OL9935718000" OLED_RITDISPLAY_9OL9935718000 56.375,27.5 r90 top locked value=9OL9935718000
U14 "ESDALC6V1W5" ESD_SOT323-5L 63.75,10.75 r270 top
U15 "ESDALC6V1W5" ESD_SOT323-5L 58.625,10.75 r270 top
U16 "LP2985IM5-3.6/NOPB" REG_SOT23-5L 17.5,26 r0 bottom
U17 "ESD-TRANSIL" ESD_QFN1610_2N_1K_2A 31.5,7.375 r180 top value=ESDA7P120-1U1M
U18 "LD1117S33TR" REG_SOT223-TAB 18.75,34 r180 bottom
U19 "LD3985M18R" REG_SOT23-5L 17.75,41.25 r180 bottom
U20 "LD1117S50TR" REG_SOT223-TAB 18.5,19.25 r270 bottom
U21 "MP23DB01MMTR" MIC_STM_MP23DB01MMTR 2.75,56.5 r90 bottom value=MP23DB01HPTR
X1 "XTAL_4_PINS" CRY_NX2016SA_4P 40.025,36.775 r270 bottom value=24MHz

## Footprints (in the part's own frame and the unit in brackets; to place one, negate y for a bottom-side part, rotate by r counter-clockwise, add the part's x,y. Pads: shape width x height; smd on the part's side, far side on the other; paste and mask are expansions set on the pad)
C0402 [mm]
  rect 0.51x0.56 smd mask+0.05: 1(-0.45,0) 2(0.45,0)
  body extent -0.5,-0.3 0.5,0.3, height 0.4
C0603 [mm]
  rect 0.64x0.89 smd mask+0.05: 1(-0.7,0) 2(0.7,0)
  silkscreen extent -0.9,-0.55 1.05,0.55, body extent -0.9,-0.5 0.9,0.5, height 1.4
C0805 [mm]
  rect 0.9x1.4 smd mask+0.05: 1(-0.85,0) 2(0.85,0)
  silkscreen extent -1.3,-0.77 1.3,0.77, body extent -1.1,-0.7 1.1,0.7, height 1.35
C0805_H0P85 [mm] "MCD-01525"
  rect 0.9x1.4 smd mask+0.05: 1(-0.85,0) 2(0.85,0)
  silkscreen extent -1.3,-0.77 1.3,0.77, body extent -1.1,-0.73 1.1,0.72, height 0.95
CON_988-JIUBABA_A2006LF-04A [mm] "MCD-01741"
  rect 1.7x3.1 smd mask+0.05: 0(-5.2,0) 0(5.2,0)
  rect 1.1x4.6 smd mask+0.05: 1(3,2.75) 2(1,2.75) 3(-1,2.75) 4(-3,2.75)
  silkscreen extent -6.12,-2.55 6.12,2.8, body extent -6.12,-2.55 6.12,4, height 8.35
CON_JST_B2B-PH-K-S [mm] "MCD-01806"
  rect 1.5x1.5 hole 0.8 mask+0.05: 1(-1,0)
  round 1.5 hole 0.8 mask+0.05: 2(1,0)
  silkscreen extent -2.95,-2.8 2.95,1.7, body extent -2.95,-2.8 2.95,1.7, height 6
CON_PHONE-JACK-3P5_HY_PJ3028B [mm]
  rect 1.5x2.5 smd mask+0.05: 2(1.25,-3.45) 7(2.85,3.45)
  rect 2x2.5 smd mask+0.05: 3(4,-3.45) 4(5.8,3.45) 6(13.2,-3.45)
  rect 2.5x2 smd mask+0.05: 5(17.25,0.75)
  round 0.5 hole 2 unplated mask+0.1: MT1(5,0) MT2(12,0)
  Multi-Layer keep-out circle w0.01: c5,0 r1.25
  Multi-Layer keep-out circle w0.01: c12,0 r1.25
  silkscreen extent -0.9,-3.7 16,3, body extent -0.9,-3 16,3, height 5
CON_SAMTEC_CLP-125-02-F-D [mm] "MCD-02705"
  rect 1.8x0.75 smd: 1(-1.5,15.24) 2(1.5,15.24) 3(-1.5,13.97) 4(1.5,13.97) 5(-1.5,12.7) 6(1.5,12.7) 7(-1.5,11.43) 8(1.5,11.43) 9(-1.5,10.16) 10(1.5,10.16) 11(-1.5,8.89) 12(1.5,8.89) 13(-1.5,7.62) 14(1.5,7.62) 15(-1.5,6.35) 16(1.5,6.35) 17(-1.5,5.08) 18(1.5,5.08) 19(-1.5,3.81) 20(1.5,3.81) 21(-1.5,2.54) 22(1.5,2.54) 23(-1.5,1.27) 24(1.5,1.27) 25(-1.5,0) 26(1.5,0) 27(-1.5,-1.27) 28(1.5,-1.27) 29(-1.5,-2.54) 30(1.5,-2.54) 31(-1.5,-3.81) 32(1.5,-3.81) 33(-1.5,-5.08) 34(1.5,-5.08) 35(-1.5,-6.35) 36(1.5,-6.35) 37(-1.5,-7.62) 38(1.5,-7.62) 39(-1.5,-8.89) 40(1.5,-8.89) 41(-1.5,-10.16) 42(1.5,-10.16) 43(-1.5,-11.43) 44(1.5,-11.43) 45(-1.5,-12.7) 46(1.5,-12.7) 47(-1.5,-13.97) 48(1.5,-13.97) 49(-1.5,-15.24) 50(1.5,-15.24)
  silkscreen extent -1.48,-16.09 1.49,16.09, body extent -2.16,-16.09 2.16,16.09, height 2.27
CON_SAMTEC_SQT-110-01-F-D-RA__STMOD+ [mm] "SQT-110-01-F-D-RA (connecteur SAMTEC pour interface STMod+ femelle coté Host) Pinning adapté non conforme SAMTEC."
  rect 1.6x1.6 hole 0.9 mask+0.05: 1(9,1)
  round 1.6 hole 0.9 mask+0.05: 2(7,1) 3(5,1) 4(3,1) 5(1,1) 6(-1,1) 7(-3,1) 8(-5,1) 9(-7,1) 10(-9,1) 11(9,-1) 12(7,-1) 13(5,-1) 14(3,-1) 15(1,-1) 16(-1,-1) 17(-3,-1) 18(-5,-1) 19(-7,-1) 20(-9,-1)
  silkscreen extent -10.15,-8.62 10.15,0.07, body extent -10.15,-8.65 10.15,1.22, height 4
CON_SAMTEC_SSM-106-L-SV [mm] "MCD-02346"
  rect 1.02x1.905 smd mask+0.05: 1(-6.35,-1.602) 2(-3.81,1.603) 3(-1.27,-1.602) 4(1.27,1.603) 5(3.81,-1.602) 6(6.35,1.603)
  silkscreen extent -7.62,-1.27 7.62,1.27, body extent -7.62,-2.29 7.62,2.29, height 7.37
CON_SAMTEC_SSM-108-L-SV [mm] "MCD-02345"
  rect 1.02x1.905 smd mask+0.05: 1(-8.89,-1.602) 2(-6.35,1.603) 3(-3.81,-1.602) 4(-1.27,1.603) 5(1.27,-1.602) 6(3.81,1.603) 7(6.35,-1.602) 8(8.89,1.603)
  silkscreen extent -10.16,-1.27 10.16,1.27, body extent -10.16,-2.29 10.16,2.29, height 7.37
CON_SAMTEC_SSM-110-L-SV [mm] "MCD-02342"
  rect 1.02x1.905 smd mask+0.05: 1(-11.43,-1.602) 2(-8.89,1.603) 3(-6.35,-1.602) 4(-3.81,1.603) 5(-1.27,-1.602) 6(1.27,1.603) 7(3.81,-1.602) 8(6.35,1.603) 9(8.89,-1.602) 10(11.43,1.603)
  silkscreen extent -12.7,-1.27 12.7,1.27, body extent -12.7,-2.29 12.7,2.29, height 7.49
CON_SAMTEC_TSW-102-07-G-S [mm]
  rect 1.85x1.85 / inner round 1.85 / far side rect 1.85x1.85 hole 1 mask+0.05: 1(-1.27,0)
  round 1.85 hole 1 mask+0.05: 2(1.27,0)
  silkscreen extent -2.58,-1.3 2.58,1.3, body extent -2.67,-1.3 2.58,1.3, height 8.38
CON_SAMTEC_TSW-103-07-F-S [mm]
  rect 1.85x1.85 / inner round 1.85 / far side rect 1.85x1.85 hole 1 mask+0.05: 1(-2.54,0)
  round 1.85 hole 1 mask+0.05: 2(0,0) 3(2.54,0)
  silkscreen extent -3.85,-1.3 3.85,1.3, body extent -3.94,-1.37 3.91,1.37, height 8.38
CON_SAMTEC_TSW-104-07-G-S [mm]
  rect 1.85x1.85 / inner round 1.85 / far side rect 1.85x1.85 hole 1 mask+0.05: 1(-3.81,0)
  round 1.85 hole 1 mask+0.05: 2(-1.27,0) 3(1.27,0) 4(3.81,0)
  silkscreen extent -5.12,-1.3 5.12,1.3, body extent -5.21,-1.37 5.18,1.37, height 8.38
CON_SAMTEC_TSW-104-07-X-D [mm]
  rect 1.85x1.85 / inner round 1.85 / far side rect 1.85x1.85 hole 1 mask+0.05: 1(-3.81,-1.27)
  round 1.85 hole 1 mask+0.05: 2(-3.81,1.27) 3(-1.27,-1.27) 4(-1.27,1.27) 5(1.27,-1.27) 6(1.27,1.27) 7(3.81,-1.27) 8(3.81,1.27)
  silkscreen extent -5.08,-2.54 5.08,2.54, body extent -5.08,-2.54 5.08,2.54, height 8.38
CON_STDC14_Receiver_MEDIUM_WITH_MIPI10_3D [mm] "compatible with FTSH-105-01-L-DV,-K and FTSH-107-01-L-DV,-K,-A,-P,-ES"
  round 0 hole 1.19 unplated mask+0.05: 0(-5.445,0) 0(5.445,0)
  round 0 hole 0.97 unplated mask+0.05: 0(-3.175,0) 0(3.175,0)
  rect 0.74x2.79 smd mask+0.05: 1(-3.81,-2.032) 2(-3.81,2.032) 3(-2.54,-2.032) 4(-2.54,2.032) 5(-1.27,-2.032) 6(-1.27,2.032) 7(0,-2.032) 8(0,2.032) 9(1.27,-2.032) 10(1.27,2.032) 11(2.54,-2.032) 12(2.54,2.032) 13(3.81,-2.032) 14(3.81,2.032)
  silkscreen extent -6.3,-4.38 6.3,3.6, body extent -6.3,-2.92 6.3,2.92, height 6.6
CON_TAG-C_TC2050-IDC-NL [mm]
  round 0.9 smd paste+0 mask+0.05: 1(-2.54,-0.635) 2(-1.27,-0.635) 3(0,-0.635) 4(1.27,-0.635) 5(2.54,-0.635) 6(2.54,0.635) 7(1.27,0.635) 8(0,0.635) 9(-1.27,0.635) 10(-2.54,0.635)
  round 0 hole 1.1 unplated mask+0.05: 11(-3.81,0) 12(3.81,-1.015) 13(3.81,1.015)
  silkscreen extent -6.22,-3.4 6.22,3.33, body extent -6.28,-3.46 6.28,3.39, height 13
CON_USB-TYPEC_WE_632723300011 [mm]
  rect 0.3x1.2 smd mask+0.05: A1(-2.75,10.58) A2(-2.25,10.58) A3(-1.75,10.58) A4(-1.25,10.58) A5(-0.75,10.58) A6(-0.25,10.58) A7(0.25,10.58) A8(0.75,10.58) A9(1.25,10.58) A10(1.75,10.58) A11(2.25,10.58) A12(2.75,10.58)
  round 0.6 hole 0.4 mask+0.05: B1(2,9.33) B1(2.8,9.33) B2(2.4,8.62) B3(1.6,8.62) B4(1.2,9.33) B5(0.8,8.62) B6(0.4,9.33) B7(-0.4,9.33) B8(-0.8,8.62) B9(-1.2,9.33) B10(-1.6,8.62) B11(-2.4,8.62) B12(-2.8,9.33) B12(-2,9.33)
  oval 1.15x1.55 hole 0.45 slot 0.85 at 90 deg mask+0.05: SH1(-4.27,8.18) SH2(-4.27,3.45) SH3(4.27,8.18) SH4(4.27,3.45)
  silkscreen extent -4.38,-0.95 4.38,10.38, body extent -4.38,-0.98 4.38,10.82, height 3.03
CPOL_TAJ-A_1206_H180 [mm]
  rect 1.45x1.6 smd mask+0.05: 1(-1.175,0) 2(1.175,0)
  silkscreen extent -2.15,-1.05 1.7,1.05, body extent -1.7,-0.9 1.7,0.9, height 1.8
CRY_NX2016SA_4P [mm]
  rect 0.85x0.75 smd mask+0.05: 1(-0.675,-0.525) 2(0.675,-0.525) 3(0.675,0.525) 4(-0.675,0.525)
  silkscreen extent -1.22,-1.02 1.05,0.85, body extent -1.05,-0.85 1.05,0.85, height 0.7
DIO_SOD323_1A_2K [mm]
  rect 1.06x0.54 smd mask+0.05: 1(-1.07,0) 2(1.07,0)
  silkscreen extent -0.9,-0.72 0.9,0.72, body extent -1.3,-0.78 1.3,0.78, height 1.17
ESD_QFN1610_2N_1K_2A [mm] "DFN, 2-Leads, Body 1.60x1.00mm"
  rect 0.55x0.9 smd mask+0.05: 1(-0.625,0) 2(0.625,0)
  silkscreen extent -1.02,-0.58 0.85,0.58, body extent -0.85,-0.55 0.85,0.55, height 0.6
ESD_QFN-6L_1P7X1P5_P050 [mm]
  rect 0.25x0.6 smd mask+0.05: 1(-0.5,-0.65) 2(0,-0.65) 3(0.5,-0.65) 4(0.5,0.65) 5(0,0.65) 6(-0.5,0.65)
  silkscreen extent -0.9,-0.8 0.9,0.8, body extent -0.9,-0.8 0.9,0.8, height 0.56
ESD_SOT23-6L [mm]
  rect 0.6x1.2 smd mask+0.05: 1(-0.95,-1.15) 2(0,-1.15) 3(0.95,-1.15) 4(0.95,1.15) 5(0,1.15) 6(-0.95,1.15)
  silkscreen extent -1.53,-0.87 1.53,0.87, body extent -1.52,-1.5 1.52,1.5, height 1.45
ESD_SOT323-5L [mm]
  rect 0.4x1.2 smd mask+0.05: 1(-0.65,-0.85) 2(0,-0.85) 3(0.65,-0.85) 4(0.65,0.85) 5(-0.65,0.85)
  silkscreen extent -1.22,-1.21 1.22,0.77, body extent -1.15,-1.05 1.15,1.05, height 1.1
ESD_ST0201 [mm]
  rect 0.425x0.33 smd mask+0.05: 1(-0.312,0) 2(0.312,0)
  silkscreen extent -0.55,-0.3 -0.5,0.3, body extent -0.34,-0.18 0.34,0.18, height 0.34
ICC_QFN32-EPAD_5X5_P050 [mm]
  oval 0.3x0.75 smd mask+0.05: 1(-1.75,-2.425) 2(-1.25,-2.425) 3(-0.75,-2.425) 4(-0.25,-2.425) 5(0.25,-2.425) 6(0.75,-2.425) 7(1.25,-2.425) 8(1.75,-2.425) 17(1.75,2.425) 18(1.25,2.425) 19(0.75,2.425) 20(0.25,2.425) 21(-0.25,2.425) 22(-0.75,2.425) 23(-1.25,2.425) 24(-1.75,2.425)
  oval 0.75x0.3 smd mask+0.05: 9(2.425,-1.75) 10(2.425,-1.25) 11(2.425,-0.75) 12(2.425,-0.25) 13(2.425,0.25) 14(2.425,0.75) 15(2.425,1.25) 16(2.425,1.75) 25(-2.425,1.75) 26(-2.425,1.25) 27(-2.425,0.75) 28(-2.425,0.25) 29(-2.425,-0.25) 30(-2.425,-0.75) 31(-2.425,-1.25) 32(-2.425,-1.75)
  rect 3.7x3.7 smd mask+0.05: 33(0,0)
  silkscreen extent -2.63,-2.63 2.63,2.63, body extent -2.55,-2.55 2.55,2.55, height 1
ICC_SOT23-5L_H1P45 [mm]
  rect 0.6x1.3 smd mask+0.05: 1(-0.95,-1.1) 2(0,-1.1) 3(0.95,-1.1) 4(0.95,1.1) 5(-0.95,1.1)
  silkscreen extent -1.75,-1.68 1.6,0.97, body extent -1.52,-1.25 1.52,1.25, height 1.45
ICC_UFBGA201_176+25_10X10_P065 [mm] "IPC"
  round 0.25 smd mask+0.038: A1(-4.55,4.55) A2(-3.9,4.55) A3(-3.25,4.55) A4(-2.6,4.55) A5(-1.95,4.55) A6(-1.3,4.55) A7(-0.65,4.55) A8(0,4.55) A9(0.65,4.55) A10(1.3,4.55) A11(1.95,4.55) A12(2.6,4.55) A13(3.25,4.55) A14(3.9,4.55) A15(4.55,4.55) B1(-4.55,3.9) B2(-3.9,3.9) B3(-3.25,3.9) B4(-2.6,3.9) B5(-1.95,3.9) B6(-1.3,3.9) B7(-0.65,3.9) B8(0,3.9) B9(0.65,3.9) B10(1.3,3.9) B11(1.95,3.9) B12(2.6,3.9) B13(3.25,3.9) B14(3.9,3.9) B15(4.55,3.9) C1(-4.55,3.25) C2(-3.9,3.25) C3(-3.25,3.25) C4(-2.6,3.25) C5(-1.95,3.25) C6(-1.3,3.25) C7(-0.65,3.25) C8(0,3.25) C9(0.65,3.25) C10(1.3,3.25) C11(1.95,3.25) C12(2.6,3.25) C13(3.25,3.25) C14(3.9,3.25) C15(4.55,3.25) D1(-4.55,2.6) D2(-3.9,2.6) D3(-3.25,2.6) D4(-2.6,2.6) D5(-1.95,2.6) D6(-1.3,2.6) D7(-0.65,2.6) D8(0,2.6) D9(0.65,2.6) D10(1.3,2.6) D11(1.95,2.6) D12(2.6,2.6) D13(3.25,2.6) D14(3.9,2.6) D15(4.55,2.6) E1(-4.55,1.95) E2(-3.9,1.95) E3(-3.25,1.95) E4(-2.6,1.95) E12(2.6,1.95) E13(3.25,1.95) E14(3.9,1.95) E15(4.55,1.95) F1(-4.55,1.3) F2(-3.9,1.3) F3(-3.25,1.3) F4(-2.6,1.3) F6(-1.3,1.3) F7(-0.65,1.3) F8(0,1.3) F9(0.65,1.3) F10(1.3,1.3) F12(2.6,1.3) F13(3.25,1.3) F14(3.9,1.3) F15(4.55,1.3) G1(-4.55,0.65) G2(-3.9,0.65) G3(-3.25,0.65) G4(-2.6,0.65) G6(-1.3,0.65) G7(-0.65,0.65) G8(0,0.65) G9(0.65,0.65) G10(1.3,0.65) G12(2.6,0.65) G13(3.25,0.65) G14(3.9,0.65) G15(4.55,0.65) H1(-4.55,0) H2(-3.9,0) H3(-3.25,0) H4(-2.6,0) H6(-1.3,0) H7(-0.65,0) H8(0,0) H9(0.65,0) H10(1.3,0) H12(2.6,0) H13(3.25,0) H14(3.9,0) H15(4.55,0) J1(-4.55,-0.65) J2(-3.9,-0.65) J3(-3.25,-0.65) J4(-2.6,-0.65) J6(-1.3,-0.65) J7(-0.65,-0.65) J8(0,-0.65) J9(0.65,-0.65) J10(1.3,-0.65) J12(2.6,-0.65) J13(3.25,-0.65) J14(3.9,-0.65) J15(4.55,-0.65) K1(-4.55,-1.3) K2(-3.9,-1.3) K3(-3.25,-1.3) K4(-2.6,-1.3) K6(-1.3,-1.3) K7(-0.65,-1.3) K8(0,-1.3) K9(0.65,-1.3) K10(1.3,-1.3) K12(2.6,-1.3) K13(3.25,-1.3) K14(3.9,-1.3) K15(4.55,-1.3) L1(-4.55,-1.95) L2(-3.9,-1.95) L3(-3.25,-1.95) L4(-2.6,-1.95) L12(2.6,-1.95) L13(3.25,-1.95) L14(3.9,-1.95) L15(4.55,-1.95) M1(-4.55,-2.6) M2(-3.9,-2.6) M3(-3.25,-2.6) M4(-2.6,-2.6) M5(-1.95,-2.6) M6(-1.3,-2.6) M7(-0.65,-2.6) M8(0,-2.6) M9(0.65,-2.6) M10(1.3,-2.6) M11(1.95,-2.6) M12(2.6,-2.6) M13(3.25,-2.6) M14(3.9,-2.6) M15(4.55,-2.6) N1(-4.55,-3.25) N2(-3.9,-3.25) N3(-3.25,-3.25) N4(-2.6,-3.25) N5(-1.95,-3.25) N6(-1.3,-3.25) N7(-0.65,-3.25) N8(0,-3.25) N9(0.65,-3.25) N10(1.3,-3.25) N11(1.95,-3.25) N12(2.6,-3.25) N13(3.25,-3.25) N14(3.9,-3.25) N15(4.55,-3.25) P1(-4.55,-3.9) P2(-3.9,-3.9) P3(-3.25,-3.9) P4(-2.6,-3.9) P5(-1.95,-3.9) P6(-1.3,-3.9) P7(-0.65,-3.9) P8(0,-3.9) P9(0.65,-3.9) P10(1.3,-3.9) P11(1.95,-3.9) P12(2.6,-3.9) P13(3.25,-3.9) P14(3.9,-3.9) P15(4.55,-3.9) R1(-4.55,-4.55) R2(-3.9,-4.55) R3(-3.25,-4.55) R4(-2.6,-4.55) R5(-1.95,-4.55) R6(-1.3,-4.55) R7(-0.65,-4.55) R8(0,-4.55) R9(0.65,-4.55) R10(1.3,-4.55) R11(1.95,-4.55) R12(2.6,-4.55) R13(3.25,-4.55) R14(3.9,-4.55) R15(4.55,-4.55)
  silkscreen extent -5.22,-5.07 5.07,5.23, body extent -5.07,-5.07 5.07,5.07, height 0.61
ICC_UFQFN16-EPAD_2P6X1P8_P040 [mm]
  rect 0.2x0.35 smd mask+0.05: 1(-0.6,-0.775) 2(-0.2,-0.775) 3(0.2,-0.775) 4(0.6,-0.775) 9(0.6,0.775) 10(0.2,0.775) 11(-0.2,0.775) 12(-0.6,0.775)
  rect 0.35x0.2 smd mask+0.05: 5(1.175,-0.6) 6(1.175,-0.2) 7(1.175,0.2) 8(1.175,0.6) 13(-1.175,0.6) 14(-1.175,0.2) 15(-1.175,-0.2) 16(-1.175,-0.6)
  rect 1.6x0.8 smd mask+0.05: 17(0,0)
  silkscreen extent -1.33,-0.92 1.33,0.92, body extent -1.33,-0.92 1.33,0.92, height 0.56
ICC_WSON8-EPAD_2X2_P050 [mm] "MCD-02194"
  rect 0.5x0.3 smd paste+0 mask+0.05: 1(-0.9,0.75) 2(-0.9,0.25) 3(-0.9,-0.25) 4(-0.9,-0.75) 5(0.9,-0.75) 6(0.9,-0.25) 7(0.9,0.25) 8(0.9,0.75)
  rect 0.9x1.6 smd paste+0 mask+0.05: 9(0,0)
  silkscreen extent -0.5,-1 0.5,1, body extent -1,-1 1,1, height 0.81
LED_0603_OSRAM_LG-Q396-PS-35_GREEN_1A2K_H0P4 [mm]
  rect 0.8x0.8 smd mask+0.05: 1(-0.75,0) 2(0.75,0)
  silkscreen extent -0.85,-0.53 1.28,0.53, body extent -0.85,-0.45 0.85,0.45, height 0.6
LED_0603_VISHAY_VLMB1300-GS08_BLUE_1A2K_H0P8 [mm]
  rect 0.8x0.8 smd mask+0.05: 1(-0.75,0) 2(0.75,0)
  silkscreen extent -0.85,-0.53 1.28,0.53, body extent -0.85,-0.45 0.85,0.45, height 0.8
LED_BI-GR_WE-150141SV73110 [mm] "MCD-02631"
  rect 1.1x1.5 smd mask+0.05: 1(-0.75,1.5) 2(0.75,1.5) 3(-0.75,-1.5) 4(0.75,-1.5)
  silkscreen extent -1.65,-1.85 1.5,1.7, body extent -1.5,-1.85 1.5,1.85, height 2.1
LINK200 [mm]
  rect 0.2x0.35 smd paste-10 mask+0.05: 1(0,-0.225) 2(0,0.225)
MIC_STM_MP23DB01MMTR [mm]
  rect 0.725x0.522 smd mask+0.05: 1(-0.838,1.364) 2(-0.838,0.542) 4(0.838,0.542) 5(0.838,1.364)
  round 0.2 smd mask+0.05: 3(0,-1.373)
  round 0 hole 0.5 unplated mask+0.05: 6(0,-0.71)
  Top Layer circle w0.3: c0,-0.71 r0.663
  silkscreen extent -1.33,-1.75 1.33,1.75, body extent -1.33,-1.76 1.33,1.75, height 1.09
MIRE_PLACE_SMD_1MM [mm]
  round 1 smd paste-10 mask+1: 1(0,0)
  Top Layer keep-out circle w0.01: c0,0 r1.5
MOS_SOT23-5L [mm]
  rect 0.6x1.3 smd mask+0.05: 1(-0.95,-1.1) 2(0,-1.1) 3(0.95,-1.1) 4(0.95,1.1) 5(-0.95,1.1)
  silkscreen extent -1.6,-0.95 1.6,0.97, body extent -1.52,-1.25 1.52,1.25, height 1.45
NPN_SOT416-FL_EMT3F_1616_SC89 [mm]
  rect 0.46x0.65 smd mask+0.05: 1(-0.5,-0.525) 2(0.5,-0.525) 3(0,0.525)
  silkscreen extent -0.85,-0.48 0.85,0.48, body extent -0.85,-0.85 0.85,0.85, height 0.85
OLED_RITDISPLAY_9OL9935718000 [mm] "OLED, 20-Leads, Body 13.86x23.74mm, Pitch 0.70mm"
  rect 0.45x3 smd mask+0.051: 1(0.45,4.5) 2(1.15,4.5) 3(1.85,4.5) 4(2.55,4.5) 5(3.25,4.5) 6(3.95,4.5) 7(4.65,4.5) 8(5.35,4.5) 9(6.05,4.5) 10(6.75,4.5) 11(7.45,4.5) 12(8.15,4.5) 13(8.85,4.5) 14(9.55,4.5) 15(10.25,4.5) 16(10.95,4.5) 17(11.65,4.5) 18(12.35,4.5) 19(13.05,4.5) 20(13.75,4.5)
  round 0.5 hole 0.8 unplated: H1(0,0) H1(14.2,0)
  Top Layer keep-out region: -0.984,1.05 1.05,1.05 1.05,-0.903 2.016,-0.903 2.016,-1.75 12.216,-1.75 12.216,-0.903 13.2,-0.903 13.2,1.05 15.216,1.05 15.216,4.597 15.216,4.697 15.14,4.88 14.999,5.021 14.815,5.097 14.716,5.097 14.275,5.097 14.275,2.35 -0.075,2.35 -0.075,5.097 -0.483,5.097 -0.582,5.098 -0.767,5.022 -0.908,4.881 -0.984,4.697 -0.984,4.597
  Keep-Out Layer circle w0.4: c0,0 r0.7
  Keep-Out Layer circle w0.4: c14.2,0 r0.7
  silkscreen extent -5.39,-1.54 19.56,17.61, body extent -5.38,-1.55 19.58,17.6, height 4.2
R0402 [mm]
  rect 0.51x0.7 smd mask+0.05: 1(-0.45,0) 2(0.45,0)
  body extent -0.52,-0.3 0.52,0.3, height 0.4
R0603 [mm]
  rect 0.64x1 smd mask+0.05: 1(-0.7,0) 2(0.7,0)
  silkscreen extent -1.05,-0.58 1.05,0.58, body extent -0.9,-0.5 0.9,0.5, height 0.56
REG_SOT23-5L [mm]
  rect 0.6x1.3 smd mask+0.05: 1(-0.95,-1.1) 2(0,-1.1) 3(0.95,-1.1) 4(0.95,1.1) 5(-0.95,1.1)
  silkscreen extent -1.6,-0.95 1.6,0.97, body extent -1.52,-1.25 1.52,1.25, height 1.1
REG_SOT223-TAB [mm]
  rect 1.5x1.65 smd mask+0.05: 1(-2.3,-3.175) 2(0,-3.175) 3(2.3,-3.175)
  rect 3.5x1.65 smd mask+0.05: 4(0,3.175)
  silkscreen extent -3.35,-2.15 3.35,2.12, body extent -3.35,-3.48 3.35,3.48, height 1.8
Sheetbox_4L2S [mil] "Sheetbox 4 layers / 2 silkscreens"
  round 20 on Mech16: 1(813.78,210.69) 1(2736.9,210.69)
SOLDER-BRIDGE_R0603-0R [mil]
  round 10 smd paste-393.7: 1(-19.69,0) 2(23.62,0)
  Top Layer region: -3.94,19.69 15.75,0 -3.94,-19.68 47.24,-19.68 47.24,19.69
  Top Layer region: -47.24,-19.68 -47.24,19.69 -17.72,19.69 1.97,0 -17.72,-19.68
  silkscreen extent -50,-23 50,23, body extent -36,-20 36,20, height 22
STICKER_BOARD_25X5 [mm] "Sticker to mention board reference + serial number"
  silkscreen extent -12.5,-2.5 12.5,2.5, body extent -12.5,-2.5 12.5,2.5, height 0.01
STICKER_PRODUCT_25X5 [mm] "Sticker to mention board CPN code"
  silkscreen extent -12.5,-2.5 12.5,2.5
SWI_C&K_KSC321GLFS_BLACK [mm] "BLACK"
  rect 3.1x1 smd mask+0.05: 1(-4.45,2) 2(4.45,2) 3(-4.45,-2) 4(4.45,-2)
  silkscreen extent -3.25,-3.25 3.25,3.25, body extent -5,-3.25 5,3.25, height 3.5
SWI_XIEJIA_MT-008A_6P [mm] "MCD-00132"
  rect 1.8x1.1 smd mask+0.05: 1(-3.1,1.4) 2(-3.1,0) 3(-3.1,-1.4) 4(3.1,1.4) 5(3.1,0) 6(3.1,-1.4)
  rect 2.2x1.4 smd mask+0.05: 7(0,3.75) 8(0,-3.75)
  round 0 hole 0.8 unplated paste-10 mask+0.05: NPTH1(0,1.9)
  round 0 hole 1.1 unplated paste-10 mask+0.05: NPTH2(0,-1.9)
  silkscreen extent -3.7,-3.7 3.7,3.7, body extent -3.85,-3.75 3.85,3.75, height 5.2
TP_SMD_0-3MM [mm]
  round 0.3 smd paste-10 mask+0.05: 1(0,0)
  silkscreen extent -0.3,-0.3 0.3,0.3
TP_SMD_1MM [mm]
  round 1 smd paste-10 mask+0.05: 1(0,0)
  silkscreen extent -0.7,-0.7 0.7,0.7

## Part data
B1: library part MCD-00132, "Joystick, 4 dir, 1 OK", Manufacturer="XIEJIA ELECTRONICS", Manufacturer_Part_Number=MT-008A
B3: library part MCD-00175, "Switch HW BLACK High3.5mm 2Newtons", Manufacturer=C&K, Manufacturer_Part_Number=KSC321GLFS
C1 C2 C3 C4 C5 C6: library part MCD-01550, "Capacitor, MLCC, 1uF, 16V, X5R, +/-10%, 0805, T=0.85mm", Manufacturer=YAGEO, Manufacturer_Part_Number=CC0805KRX5R7BB105, Package=0805
C7 C8 C9 C10 C11 C44 C46: library part MCD-02355, "Capacitor, MLCC, 100nF, 25V, X7R, +/-10%, 0402, T=0.5mm", Manufacturer=WALSIN, Manufacturer_Part_Number=0402B104K250CT, Package=0402
C12 C26 C88: library part MCD-00095, "Capacitor, MLCC, 1uF, 25V, X5R, +/-10%, 0402, T=0,5mm", Alternate_Manufacturer=MURATA, Alternate_Manufacturer_Part_Number=GRM155R60J105KE19, Manufacturer_Part_Number=GRM155R61E105KA12, Package=C0402
C13: library part MCD-00011, "Capacitor, MLCC, 10nF, 16V, X7R, +/-10%, 0402, T=0.5mm", Alternate_Manufacturer=N/A, Manufacturer=YAGEO, Manufacturer_Part_Number=CC0402KRX7R7BB103, Package=0402
C14 C87: library part MCD-00694, "Capacitor, MLCC, 1.8nF, 50V, X7R, +/-10%, 0402, T=0.5mm", Manufacturer=YAGEO, Manufacturer_Part_Number=CC0402KRX7R9BB182, Package=0402
C15: library part MCD-00006, "Capacitor, MLCC, 100nF, 16V, X7R, 10%, 0402, T=0.5mm", Manufacturer=YAGEO, Manufacturer_Part_Number=CC0402KRX7R7BB104, Package=C0402
C16 C18 C24 C25 C28 C32 C34 C85 C86: library part MCD-01722, "Capacitor, 1uF, 10V, X5R, 10%, 0402, T=0.5mm", Manufacturer=YAGEO, Manufacturer_Part_Number=CC0402KRX5R6BB105, Package=C0402
C17 C19 C20 C22 C27: library part MCD-00102, "Capacitor, MLCC, 100nF, 16V, X7R, 10%, 0402, T=0,5mm", Alternate_Manufacturer=MURATA, Alternate_Manufacturer_Part_Number=GCM155R71C104KA55D, Manufacturer=YAGEO, Manufacturer_Part_Number=CC0402KRX7R7BB104, Package=C0402
C21 C23: library part MCD-00555, "Capacitor, MLCC, 22nF, 10%, 25V, X7R, 0603, T=0,8mm", Manufacturer=YAGEO, Manufacturer_Part_Number=CC0603KRX7R8BB223, Package=C0603
C29 C30: library part MCD-00672, "Capacitor, MLCC, 150pF, 50V, NPO, 5%, 0402, T=0,5mm", Manufacturer=YAGEO, Manufacturer_Part_Number=CC0402JRNPO9BN151, Package=C0402
C31: library part MCD-00098, "Capacitor, MLCC, 10uF, 6V3, X5R, 10%, 0603, T=0,8mm", Manufacturer=YAGEO, Manufacturer_Part_Number=CC0603KRX5R5BB106, Package=C0603
C33: library part MCD-00102, "Capacitor, MLCC, 100nF, 16V, X7R, +/-10%, 0402, T=0,5mm", Alternate_Manufacturer=MURATA, Alternate_Manufacturer_Part_Number=GCM155R71C104KA55D, Manufacturer=YAGEO, Manufacturer_Part_Number=CC0402KRX7R7BB104, Package=C0402
C35: library part MCD-00205, "Capacitor, MLCC, 100pF, 50V, NPO, +/-5%, 0402, T=0.5mm", Manufacturer=YAGEO, Manufacturer_Part_Number=CC0402JRNPO9BN101, Package=0402
C36: library part MCD-00016, "Capacitor, MLCC, 20pF, 50V, NPO, +/- 5%, 0402, T=0.5mm", Manufacturer=YAGEO, Manufacturer_Part_Number=CC0402JRNPO9BN200, Package=0402
C37 C38 C45: library part MCD-02198, "Capacitor, MLCC, 10nF, 50V, X7R, +/-10%, 0402, T=0.5mm", Manufacturer=YAGEO, Manufacturer_Part_Number=CC0402KRX7R9BB103, Package=0402
C39 C40: library part MCD-01774, "Capacitor, MLCC, 2.7pF, 50V, NPO, +/-0.1pF, 0402, T=0.5mm", Manufacturer=YAGEO, Manufacturer_Part_Number=CC0402BRNPO9BN2R7, Package=0402
C41 C50 C51 C52 C53 C54 C55 C56 C57 C58 C61 C62 C63 C64 C65 C66 C67 C68: library part MCD-00006, "Capacitor, MLCC, 100nF, 16V, X7R, +/-10%, 0402, T=0.5mm", Manufacturer=YAGEO, Manufacturer_Part_Number=CC0402KRX7R7BB104, Package=0402
C42 C48 C49: library part MCD-02606, "Capacitor, MLCC, 2.2uF, 6.3V, X5R, +/-10%, 0402, T=0.5mm", Manufacturer=YAGEO, Manufacturer_Part_Number=CC0402KRX5R5BB225, Package=0402
C43 C47 C60: library part MCD-00099, "Capacitor, MLCC, 10uF, 10V, X5R, +/-10%, 0603, T=0.8mm", Manufacturer=MURATA, Manufacturer_Part_Number=GRM188R61A106KE69D, Package=0603
C59: library part MCD-02372, "Capacitor, MLCC, 2.2uF, 25V, X7R, +/-10%, 0805, T=1,25mm", Manufacturer=MURATA, Manufacturer_Part_Number=GRM21BR71E225KE11L, Package=0805
C69: library part MCD-00006, "Capacitor,100nF,16V,X7R,10%,0402", Manufacturer=YAGEO, Manufacturer_Part_Number=CC0402KRX7R7BB104, Package=C0402
C70 C71 C72 C74 C75 C78: library part MCD-00010, "Capacitor, MLCC, 1uF, 16V, X5R, 10%, 0603, T=0,8mm", Manufacturer=YAGEO, Manufacturer_Part_Number=CC0603KRX5R7BB105, Package=C0603
C73 C76: library part MCD-01043, "Capacitor, Tantalum, 4.7µF, 25V, 10%, 1206", Manufacturer=VISHAY, Manufacturer_Part_Number=293D475X9025A2TE3, Package=CPOL_TAJ-A_1206_H180
C77: library part MCD-00654, "Capacitor,2.2uF,16V, X5R,10%,0603,YAGEO", Manufacturer=YAGEO, Manufacturer_Part_Number=CC0603KRX5R7BB225, Package=C0603
C79 C82: library part MCD-00011, "Capacitor, MLCC, 10nF, 16V, X7R, 10%, 0402, T=0.5mm", Manufacturer=YAGEO, Manufacturer_Part_Number=CC0402KRX7R7BB103, Package=C0402
C80 C81 C83 C84: library part MCD-00099, "Capacitor, MLCC, 10uF, 10V, X5R, 10%, 0603, T=0,8mm", Manufacturer=MURATA, Manufacturer_Part_Number=GRM188R61A106KE69D, Package=C0603
CN1 CN2: library part MCD-02705, "Socket, 25x2, 1.27mm, VR, SMD, T=2.29mm", Manufacturer=SAMTEC
CN3 CN4: library part MCD-00263, "Connector Jack Socket Stereo 3.5mm, 4 pins, RA, SMT, Black", Manufacturer=QIAOD, Manufacturer_Part_Number=PJ3028B-3_4P
CN6: library part MCD-02273, "Connector_USB_TypeC, 24pins, RA, TH, T=1.9mm (USB certified)", Manufacturer="WURTH ELEKTRONIK", Manufacturer_Part_Number=632723300011
CN7: library part MCD-00029, "Header, 4x1, 2.54mm, VR, TH, T=5.84mm/2.54mm", Manufacturer=SAMTEC, Manufacturer_Part_Number=TSW-104-07-G-S
CN8: library part MCD-02342, "Socket, 10x1, 2.54mm, VR, SMT, Height 7.37mm", Manufacturer=SAMTEC, Manufacturer_Part_Number=SSM-110-L-SV, Package="Surface Mount"
CN9 CN10: library part MCD-02345, "Socket, 8x1, 2.54mm, VR, SMT, Height 7.37mm", Manufacturer=SAMTEC, Manufacturer_Part_Number=SSM-108-L-SV, Package="Surface Mount"
CN11: library part MCD-02346, "Socket, 6x1, 2.54mm, VR, SMT, Height 7.37mm", Manufacturer=SAMTEC, Manufacturer_Part_Number=SSM-106-L-SV, Package="Surface Mount"
CN12: library part MCD-00309, "Socket 10x2, 2.00mm, RA, TH, Height 6.35mm/2.29mm", Manufacturer=SAMTEC, Manufacturer_Part_Number=SQT-110-01-F-D-RA
CN13: library part MCD-03083, "GROVE female header, SMD, 4 POS, 2.0mm", Manufacturer="SEEED TECHNOLOGY", Manufacturer_Part_Number=114020161, Package=NA
CN14: library part MCD-01226, "Header 5x2, 1.27mm, Dual row, Straight, Surface mount, vertical male connector. 3.05mm lead. Mates with FFSD connector. Footprint compatible with FTSH-107-01-L-DV,-K,-A,-P,-ES (STDC14 MEDIUM)", Manufacturer=SAMTEC, Manufacturer_Part_Number=FTSH-105-01-L-DV-K
CN15: library part MCD-00031, "Header_Plug-of-nails, 5x2, 1.27mm, No legs", Manufacturer=N/A
CN16: library part MCD-01806, "Header 2x1, 2 mm", Manufacturer=JTS, Manufacturer_Part_Number=B2B-PH-K-S
D1 D2: library part MCD-03011, "Signal Schottky Diode, If=1A, Ifsm=5A, Vf =0.54V@1A, Vrrm=23V, Ir = 0.65µA@5V, SOD-323", Manufacturer=STMICROELECTRONICS, Manufacturer_Part_Number=BAT20JFILM, Package=SOD-323
HW1: library part MCD-02707, "PCB 2L2S of NUCLEO64 for MiniBoard", Manufacturer=EMS, Manufacturer_Part_Number=MB1801, Package=PCB
HW2: library part MCD-02190, "Sticker board 25x5 mm", Manufacturer=N/A
JP1 JP6: library part MCD-00045, "Header, 2x1, 2.54mm, VR, TH, T=5.84mm/2.54mm", Manufacturer=SAMTEC, Manufacturer_Part_Number=TSW-102-07-G-S
JP2 JP5: library part MCD-00045, "Header, 2x1, 2,54mm, VR, TH, Height 5.84mm/2.54mm", Manufacturer=SAMTEC, Manufacturer_Part_Number=TSW-102-07-x-S
JP3 JP7: library part MCD-00684, "Header, 3x1, 2,54mm, VR, TH, Height 5.84mm/2.54mm - Shunt Fitted 1-2 by default", Manufacturer=SAMTEC, Manufacturer_Part_Number=TSW-103-07-F-S
JP4: library part MCD-00686, "Header, 4x2, 2.54mm, VR, TH, T=5.84mm/2.54mm", Manufacturer=SAMTEC, Manufacturer_Part_Number=TSW-104-07-G-D
LD1 LD2: library part MCD-02631, "LED Bicolor, Green/Red, 2V, 20mA,  4-PLCC", Manufacturer="WURTH ELEKTRONIK", Manufacturer_Part_Number=150141SV73110, Package=4-PLCC
LD3: library part MCD-00584, "LED Blue, 0603 SMD, 3.3 V Forward Voltage", Manufacturer=VISHAY, Manufacturer_Part_Number=VLMB1300-GS08, Package="LED 0603"
LD4: library part MCD-00588, "LED Green, 0603 SMD, Forward Voltage Typ=2V, Max=2.5V", Alternate_Manufacturer="VISHAY SEMICONDUCTOR OPTO DIVISION", Alternate_Manufacturer_Part_Number=VLMTG1300-GS08, Manufacturer="OSRAM OPTO SEMICONDUCTORS", Manufacturer_Part_Number="LG Q396-PS-35", Package="LED 0603"
LNK1: library part MCD-02777, "Track link on PCB 200um width for layout routing. No component assembly and no component in BOM", Manufacturer=STM, Package=LNK200
Q1: library part MCD-00280, "Buffer transistor", Manufacturer=ROHM
R1: library part MCD-00333, "Resistor, 5K1, 0402, +/-1%, 1/16W", Alternate_Manufacturer=N/A, Manufacturer=YAGEO, Manufacturer_Part_Number=RC0402FR-075K1L, Package=0402
R2: library part MCD-00409, "Resistor, 1K8, 0402, +/-1%, 1/16W", Alternate_Manufacturer=N/A, Manufacturer=YAGEO, Manufacturer_Part_Number=RC0402FR-071K8L, Package=0402
R3: library part MCD-00527, "Resistor, 820R, 0402, +/-1%, 1/16W", Alternate_Manufacturer=N/A, Manufacturer=YAGEO, Manufacturer_Part_Number=RC0402FR-07820RL, Package=0402
R4: library part MCD-00064, "Resistor, 510R, 0402, +/-1%, 1/16W", Alternate_Manufacturer=N/A, Manufacturer=YAGEO, Manufacturer_Part_Number=RC0402FR-07510RL, Package=0402
R5: library part MCD-00220, "Resistor,10K,0603,1%,1/10W", Manufacturer=YAGEO, Manufacturer_Part_Number=RC0603FR-0710KL, Package=R0603
R6 R12 R47 R50: library part MCD-00067, "Resistor, 100R, 0402, +/- 1%, 1/16W", Manufacturer=YAGEO, Manufacturer_Part_Number=RC0402FR-07100RL, Package=0402
R7 R10 R53: library part MCD-00059, "Resistor,100K,0402,1%,1/16W", Alternate_Manufacturer=YAGEO, Alternate_Manufacturer_Part_Number=RT0402FRE07100KL, Manufacturer_Part_Number=RC0402FR-07100KL, Package=R0402
R8 R9: library part MCD-00065, "Resistor,4K7,0402,1%,1/16W", Alternate_Manufacturer=YAGEO, Alternate_Manufacturer_Part_Number=RT0402FRE074K7L, Manufacturer_Part_Number=RC0402FR-074K7L, Package=R0402
R11 R15 R22 R30: library part MCD-00333, "Resistor, 5K1, 0402, +/-1%, 1/16W", Manufacturer=YAGEO, Manufacturer_Part_Number=RC0402FR-075K1L, Package=0402
R13 R14 R34 R39 R40: library part MCD-00059, "Resistor, 100K, 0402, +/-1%, 1/16W", Manufacturer=YAGEO, Manufacturer_Part_Number=RC0402FR-07100KL, Package=0402
R16 R18 R19 R21 R57: library part MCD-00455, "Resistor, 33R, 0402, +/-1%, 1/16W", Manufacturer=YAGEO, Manufacturer_Part_Number=RC0402FR-0733RL, Package=0402
R17 R20 R24 R58: library part MCD-00052, "Resistor, 0R, 0402, +/-5%, 1/16W", Manufacturer=YAGEO, Manufacturer_Part_Number=RC0402JR-070RL, Package=0402
R23 R26 R27 R28: library part MCD-00053, "Resistor, 10K, 0402, +/-1%, 1/16W", Manufacturer=YAGEO, Manufacturer_Part_Number=RC0402FR-0710KL, Package=0402
R25 R29: library part MCD-00185, "Resistor, 3K, 0402, +/-1%, 1/16W", Manufacturer=YAGEO, Manufacturer_Part_Number=RC0402FR-073KL, Package=0402
R31: library part MCD-00409, "Resistor, 1K8, 0402, +/-1%, 1/16W", Manufacturer=YAGEO, Manufacturer_Part_Number=RC0402FR-071K8L, Package=0402
R32: library part MCD-00381, "Resistor, 1K3, 0402, +/-1%, 1/16W", Manufacturer=YAGEO, Manufacturer_Part_Number=RC0402FR-071K3L, Package=0402
R33: library part MCD-02455, "Resistor, 3K9, 0402, +/-1%, 1/16W, +/-100ppm/°C", Manufacturer=YAGEO, Manufacturer_Part_Number=RC0402FR-073K9L, Package=0402
R35 R37: library part MCD-02665, "Resistor, 1K, 0402, +/-0.1%, 1/16W, +/-25ppm/°C", Manufacturer=YAGEO, Manufacturer_Part_Number=RT0402BRD071KL, Package=0402
R36 R38: library part MCD-00062, "Resistor, 330R, 0402, +/-1%, 1/16W", Manufacturer=YAGEO, Manufacturer_Part_Number=RC0402FR-07330RL, Package=0402
R41: library part MCD-00064, "Resistor,510R,0402,1%,1/16W", Manufacturer=YAGEO, Manufacturer_Part_Number=RC0402FR-07510RL, Package=R0402
R42 R44: library part MCD-00052, "Resistor,0R,0402,5%,1/16W", Manufacturer=YAGEO, Manufacturer_Part_Number=RC0402JR-070RL, Package=R0402
R43: library part MCD-00061, "Resistor,1K,0402,1%,1/16W", Manufacturer=YAGEO, Manufacturer_Part_Number=RC0402FR-071KL, Package=R0402
R45 R49 R55: library part MCD-00053, "Resistor,10K,0402,1%,1/16W", Manufacturer=YAGEO, Manufacturer_Part_Number=RC0402FR-0710KL, Package=R0402
R46: library part MCD-00506, "Resistor,620K,0603,1%,1/10W", Manufacturer=YAGEO, Manufacturer_Part_Number=RC0603FR-07620KL, Package=R0603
